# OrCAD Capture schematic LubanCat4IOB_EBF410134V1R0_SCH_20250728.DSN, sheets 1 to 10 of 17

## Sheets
1 17 TYPE C Socket: size A3; title: 野火_EBF RK3588S BTB底板; rev: V0R3; note: TYPE C Socket; note: https://yehuosm.tmall.com
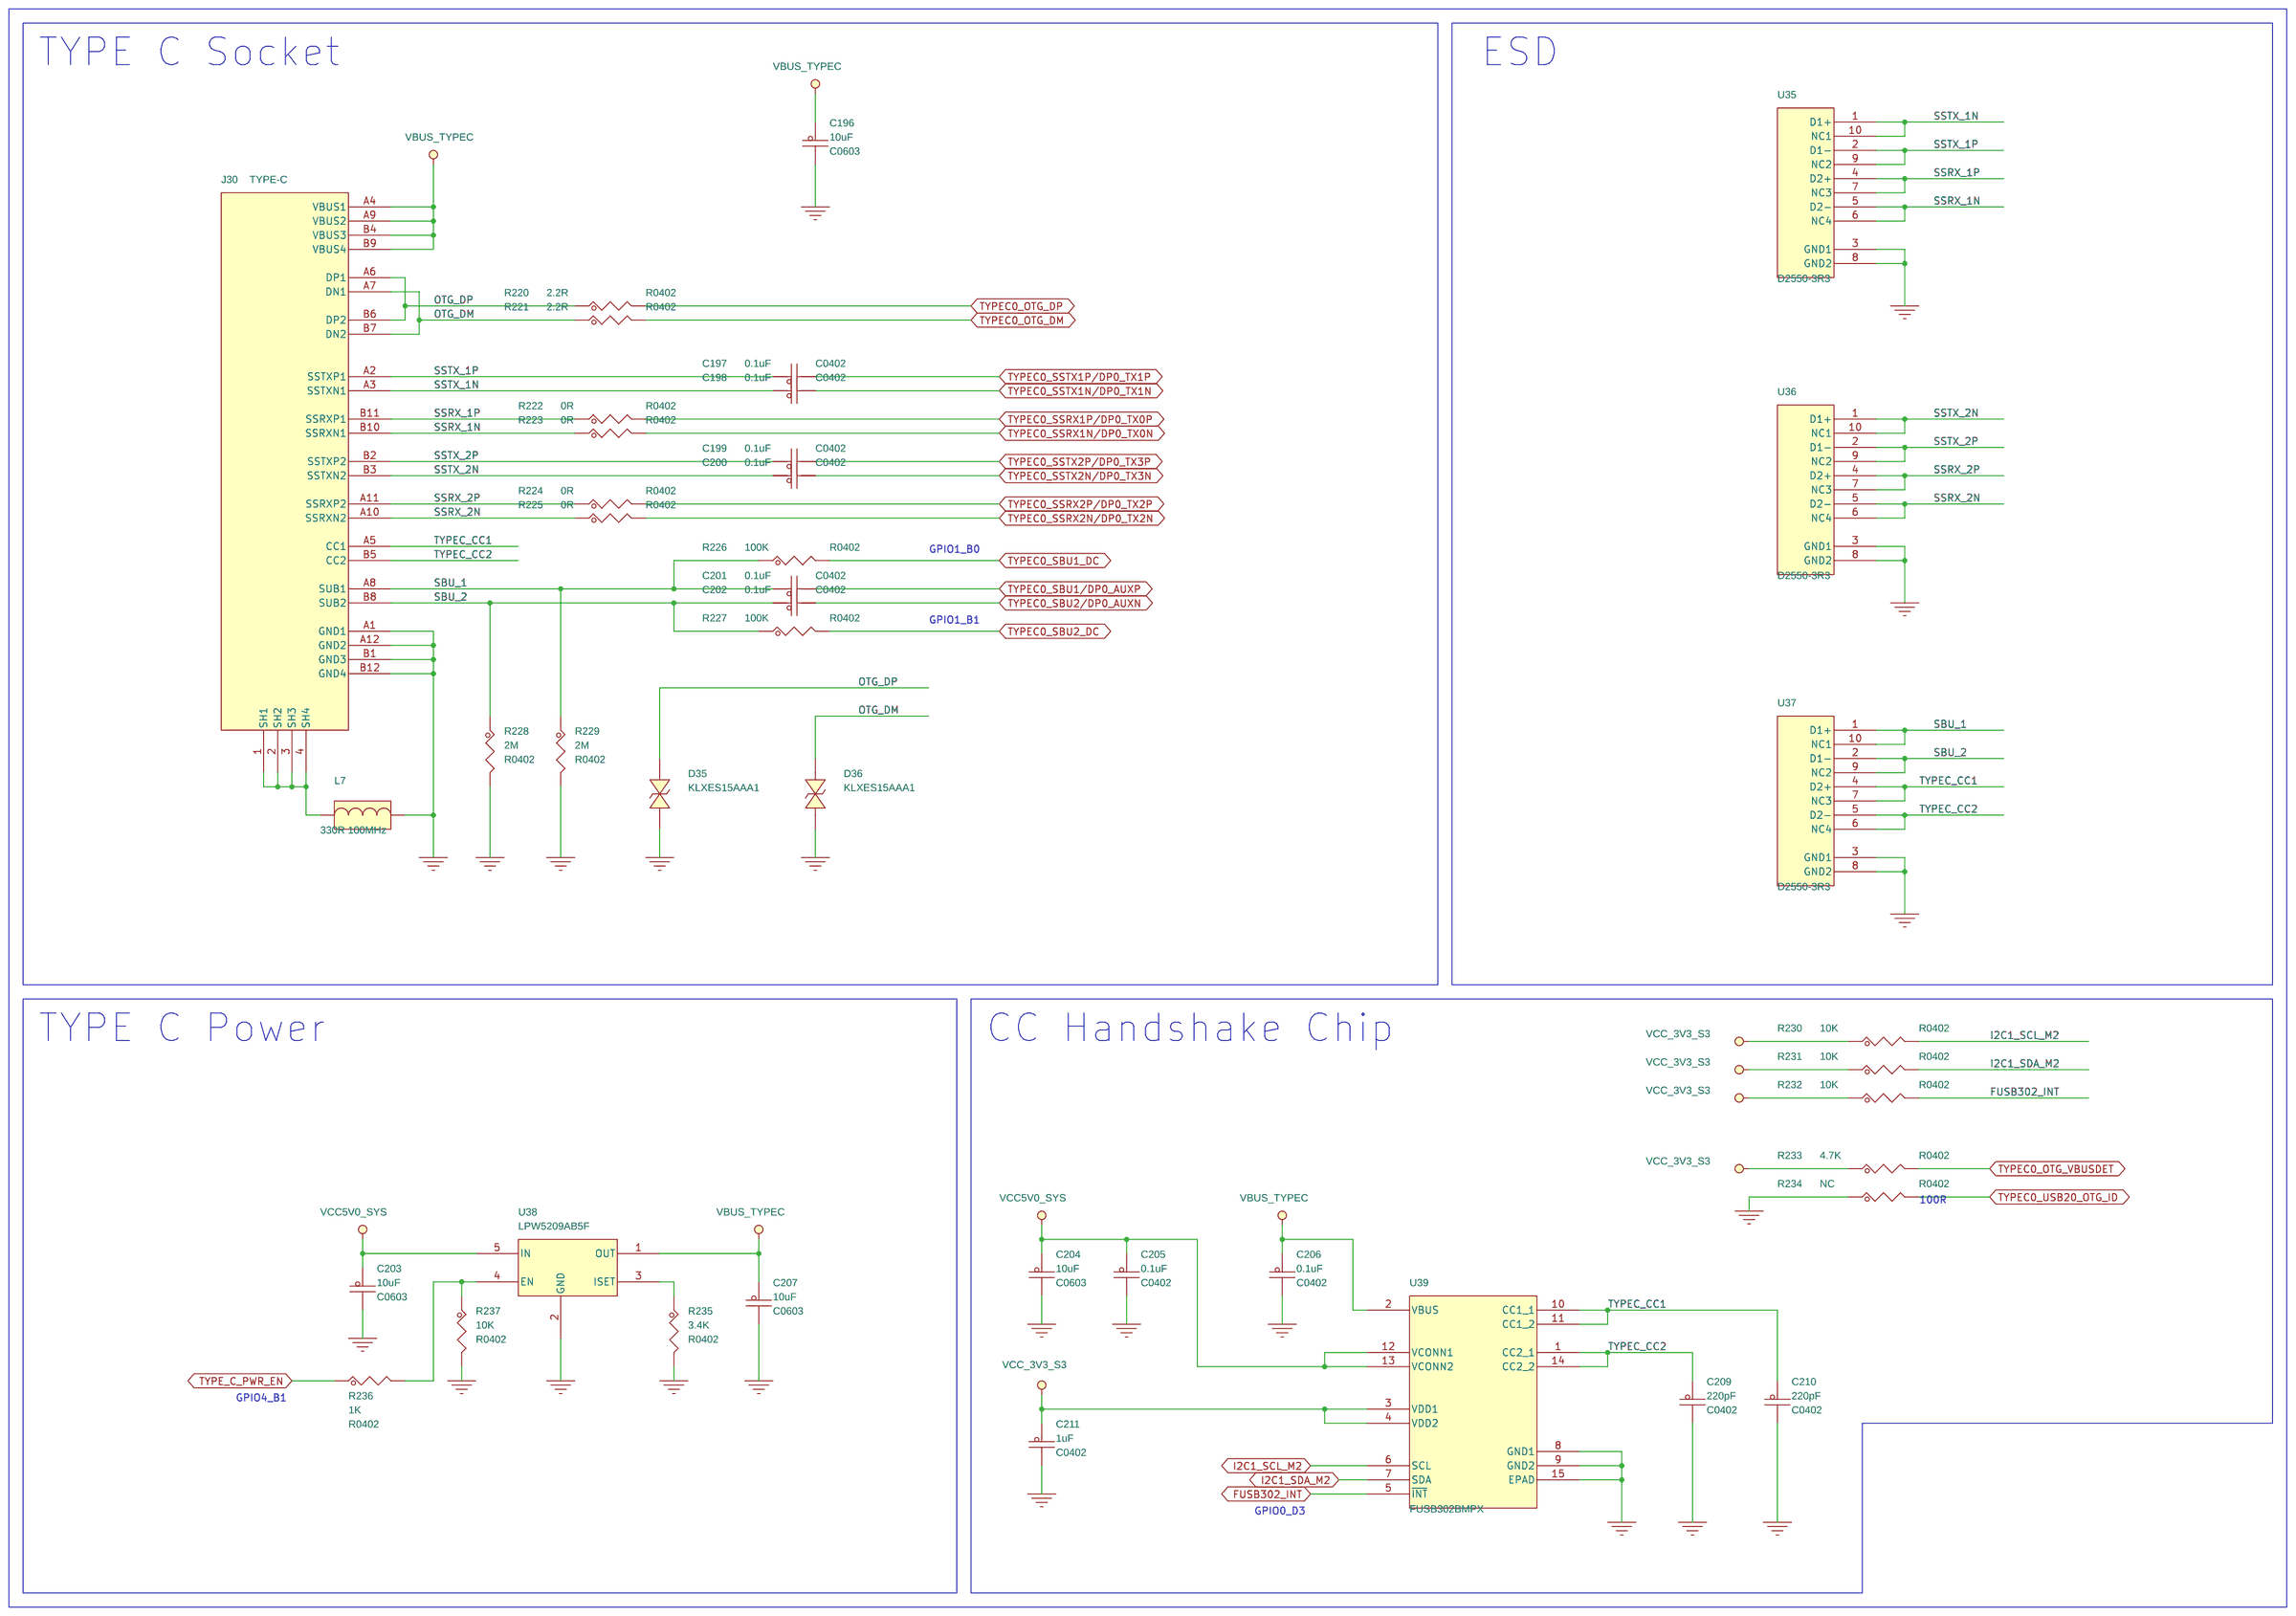
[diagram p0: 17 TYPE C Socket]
2 10 WLAN & BT: size A4; note: WLAN & BT
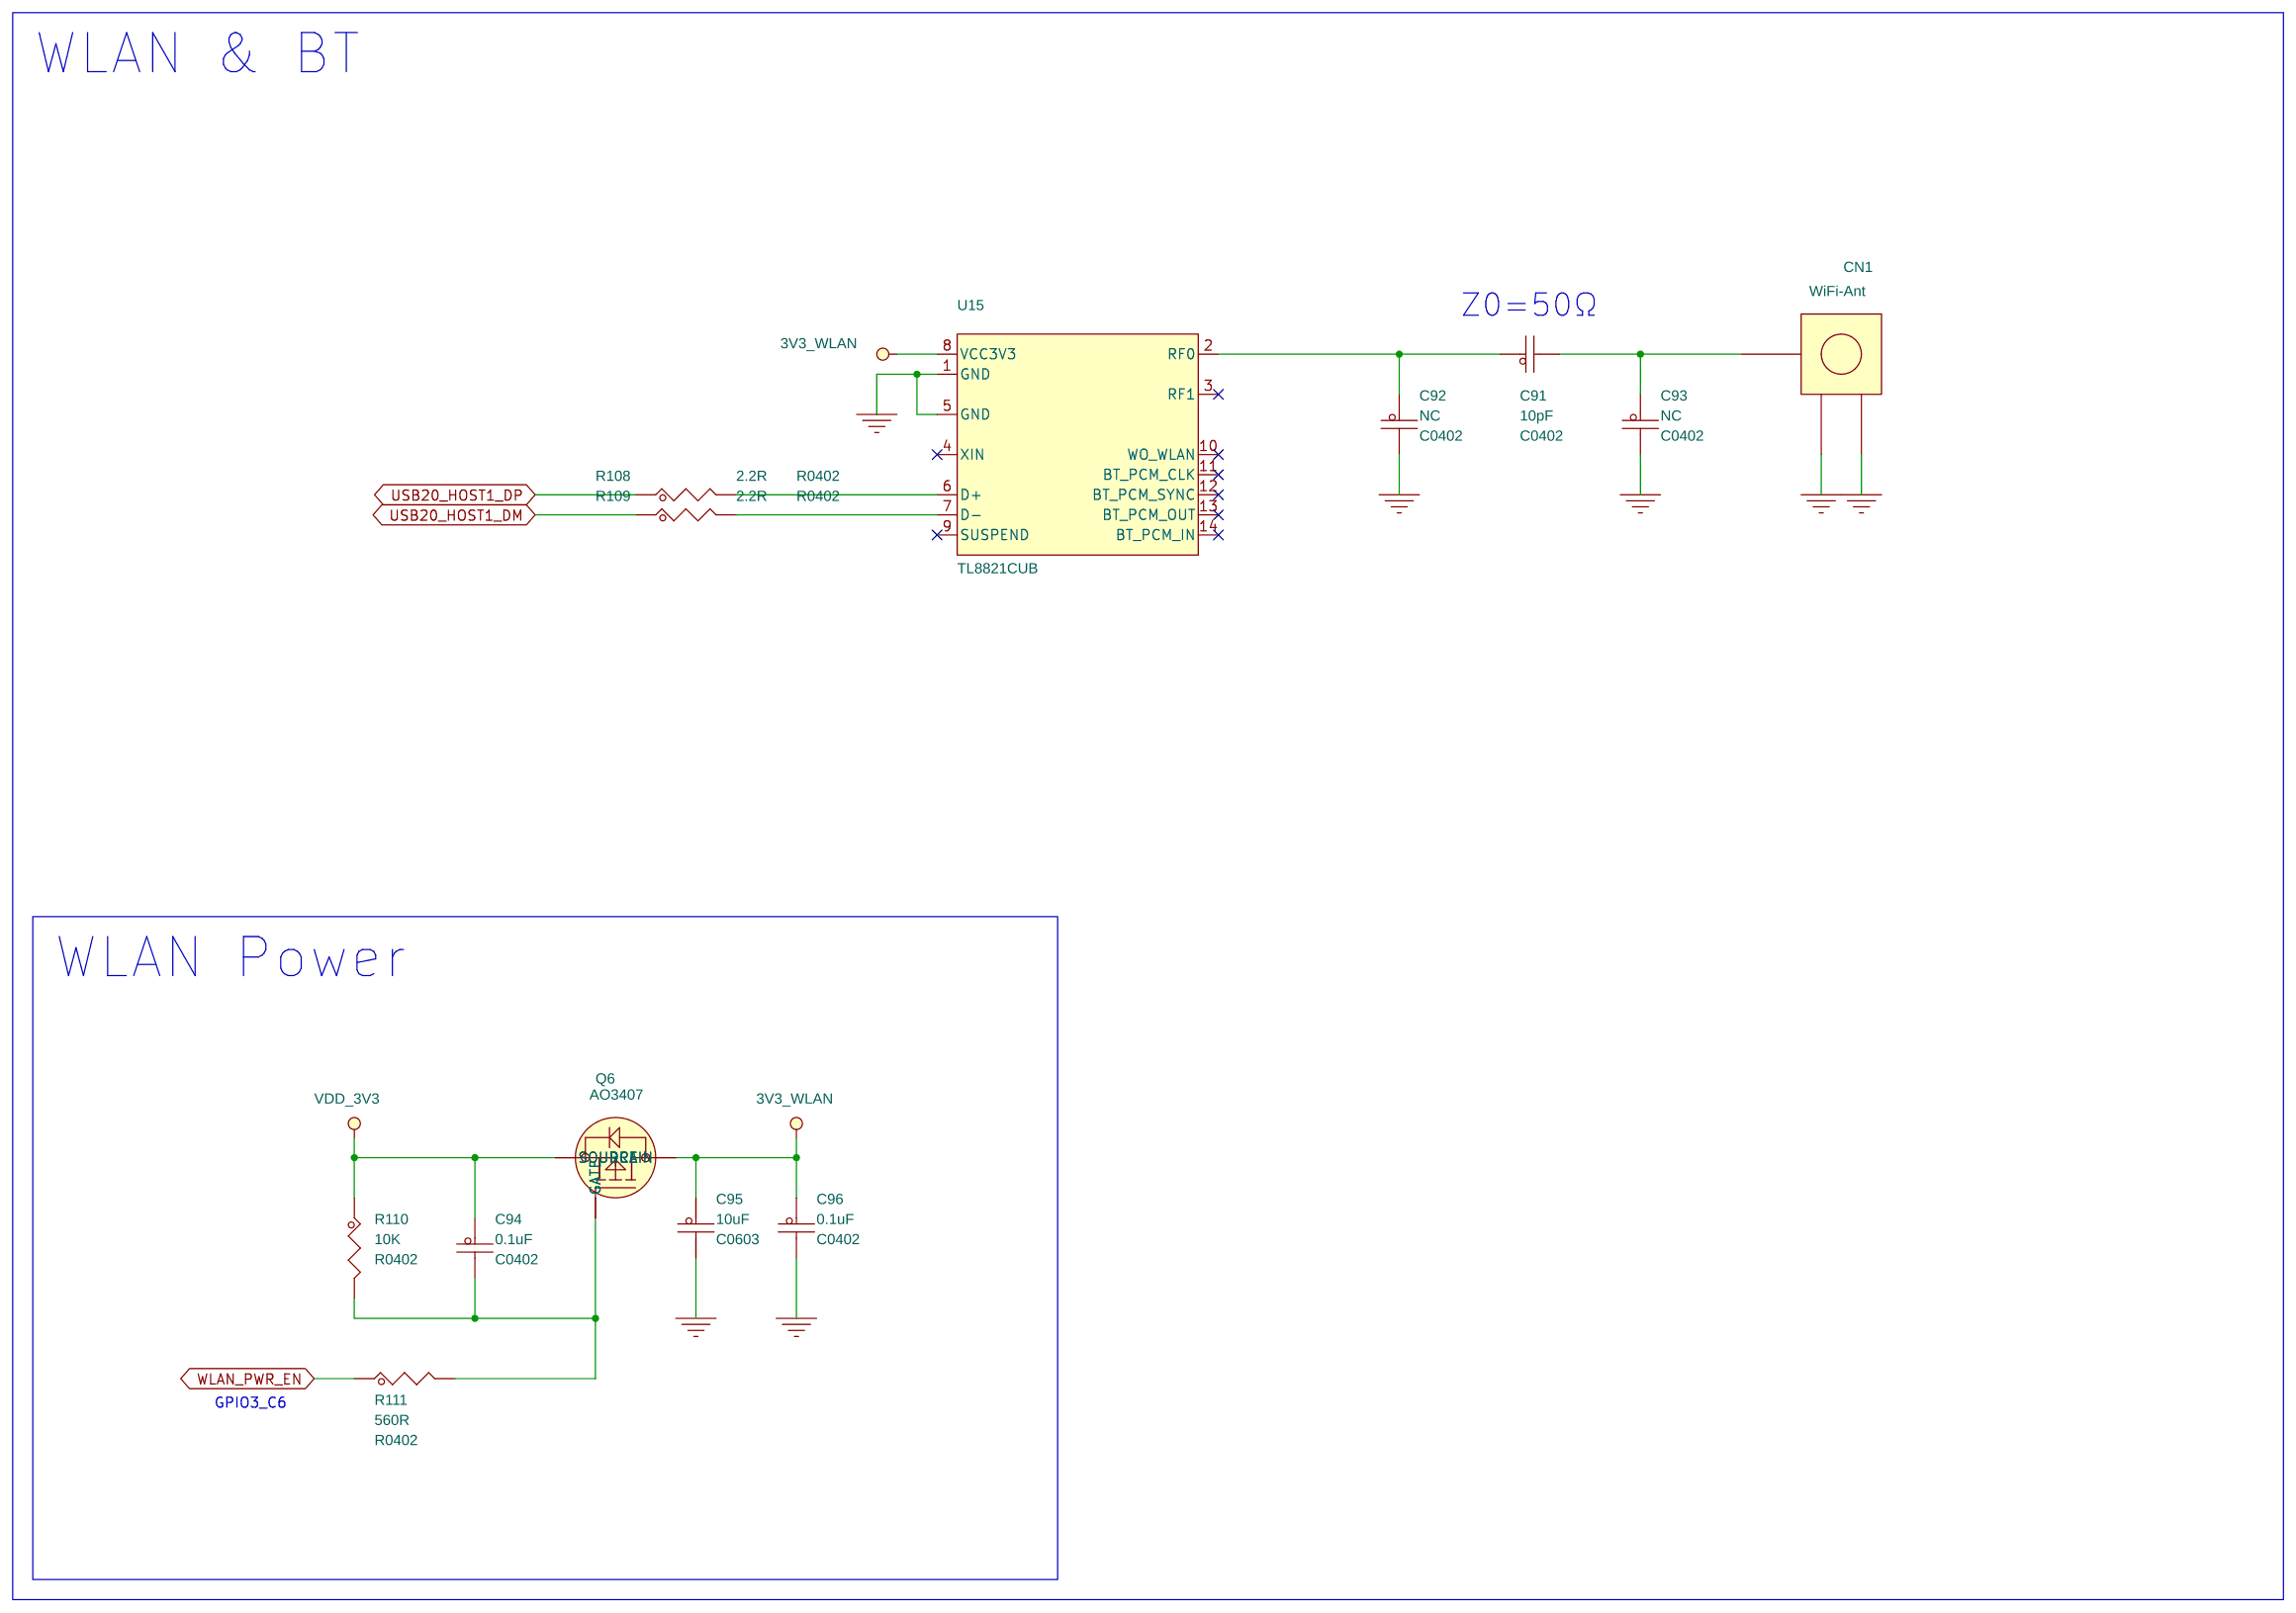
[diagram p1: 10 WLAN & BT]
3 01 Content: note: Content
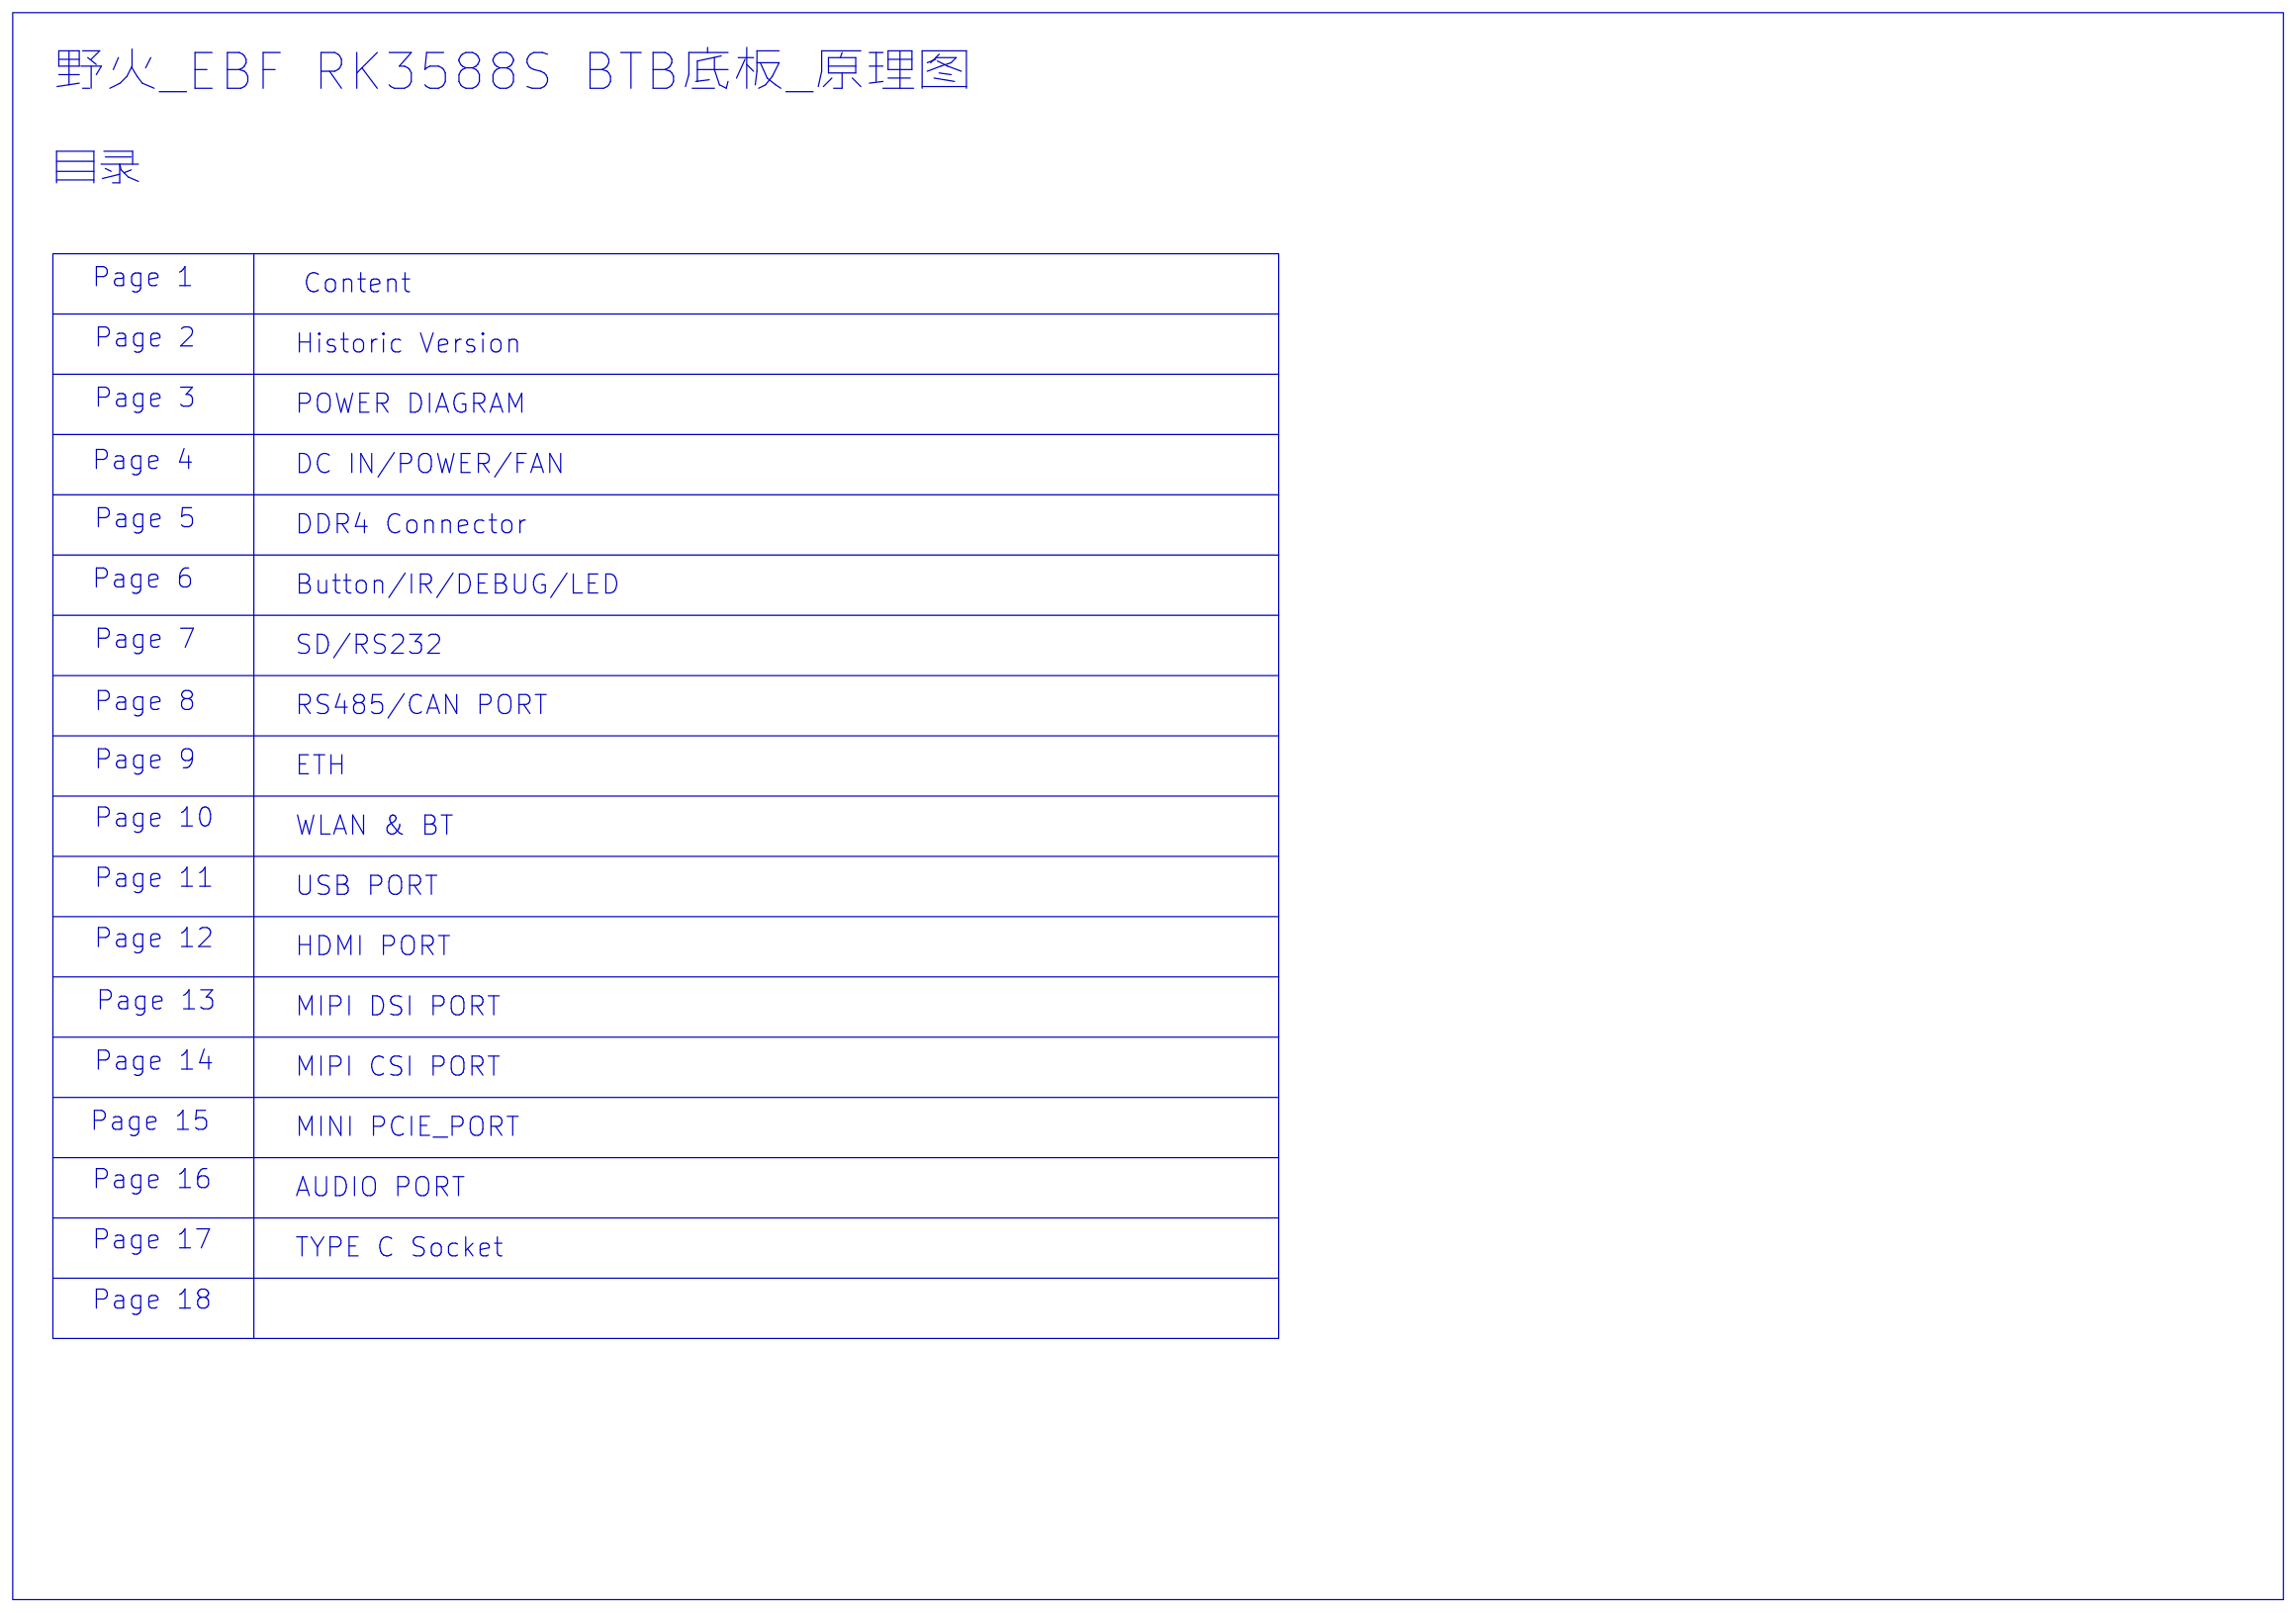
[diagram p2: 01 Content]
4 02 Historic Version: note: Historic Version
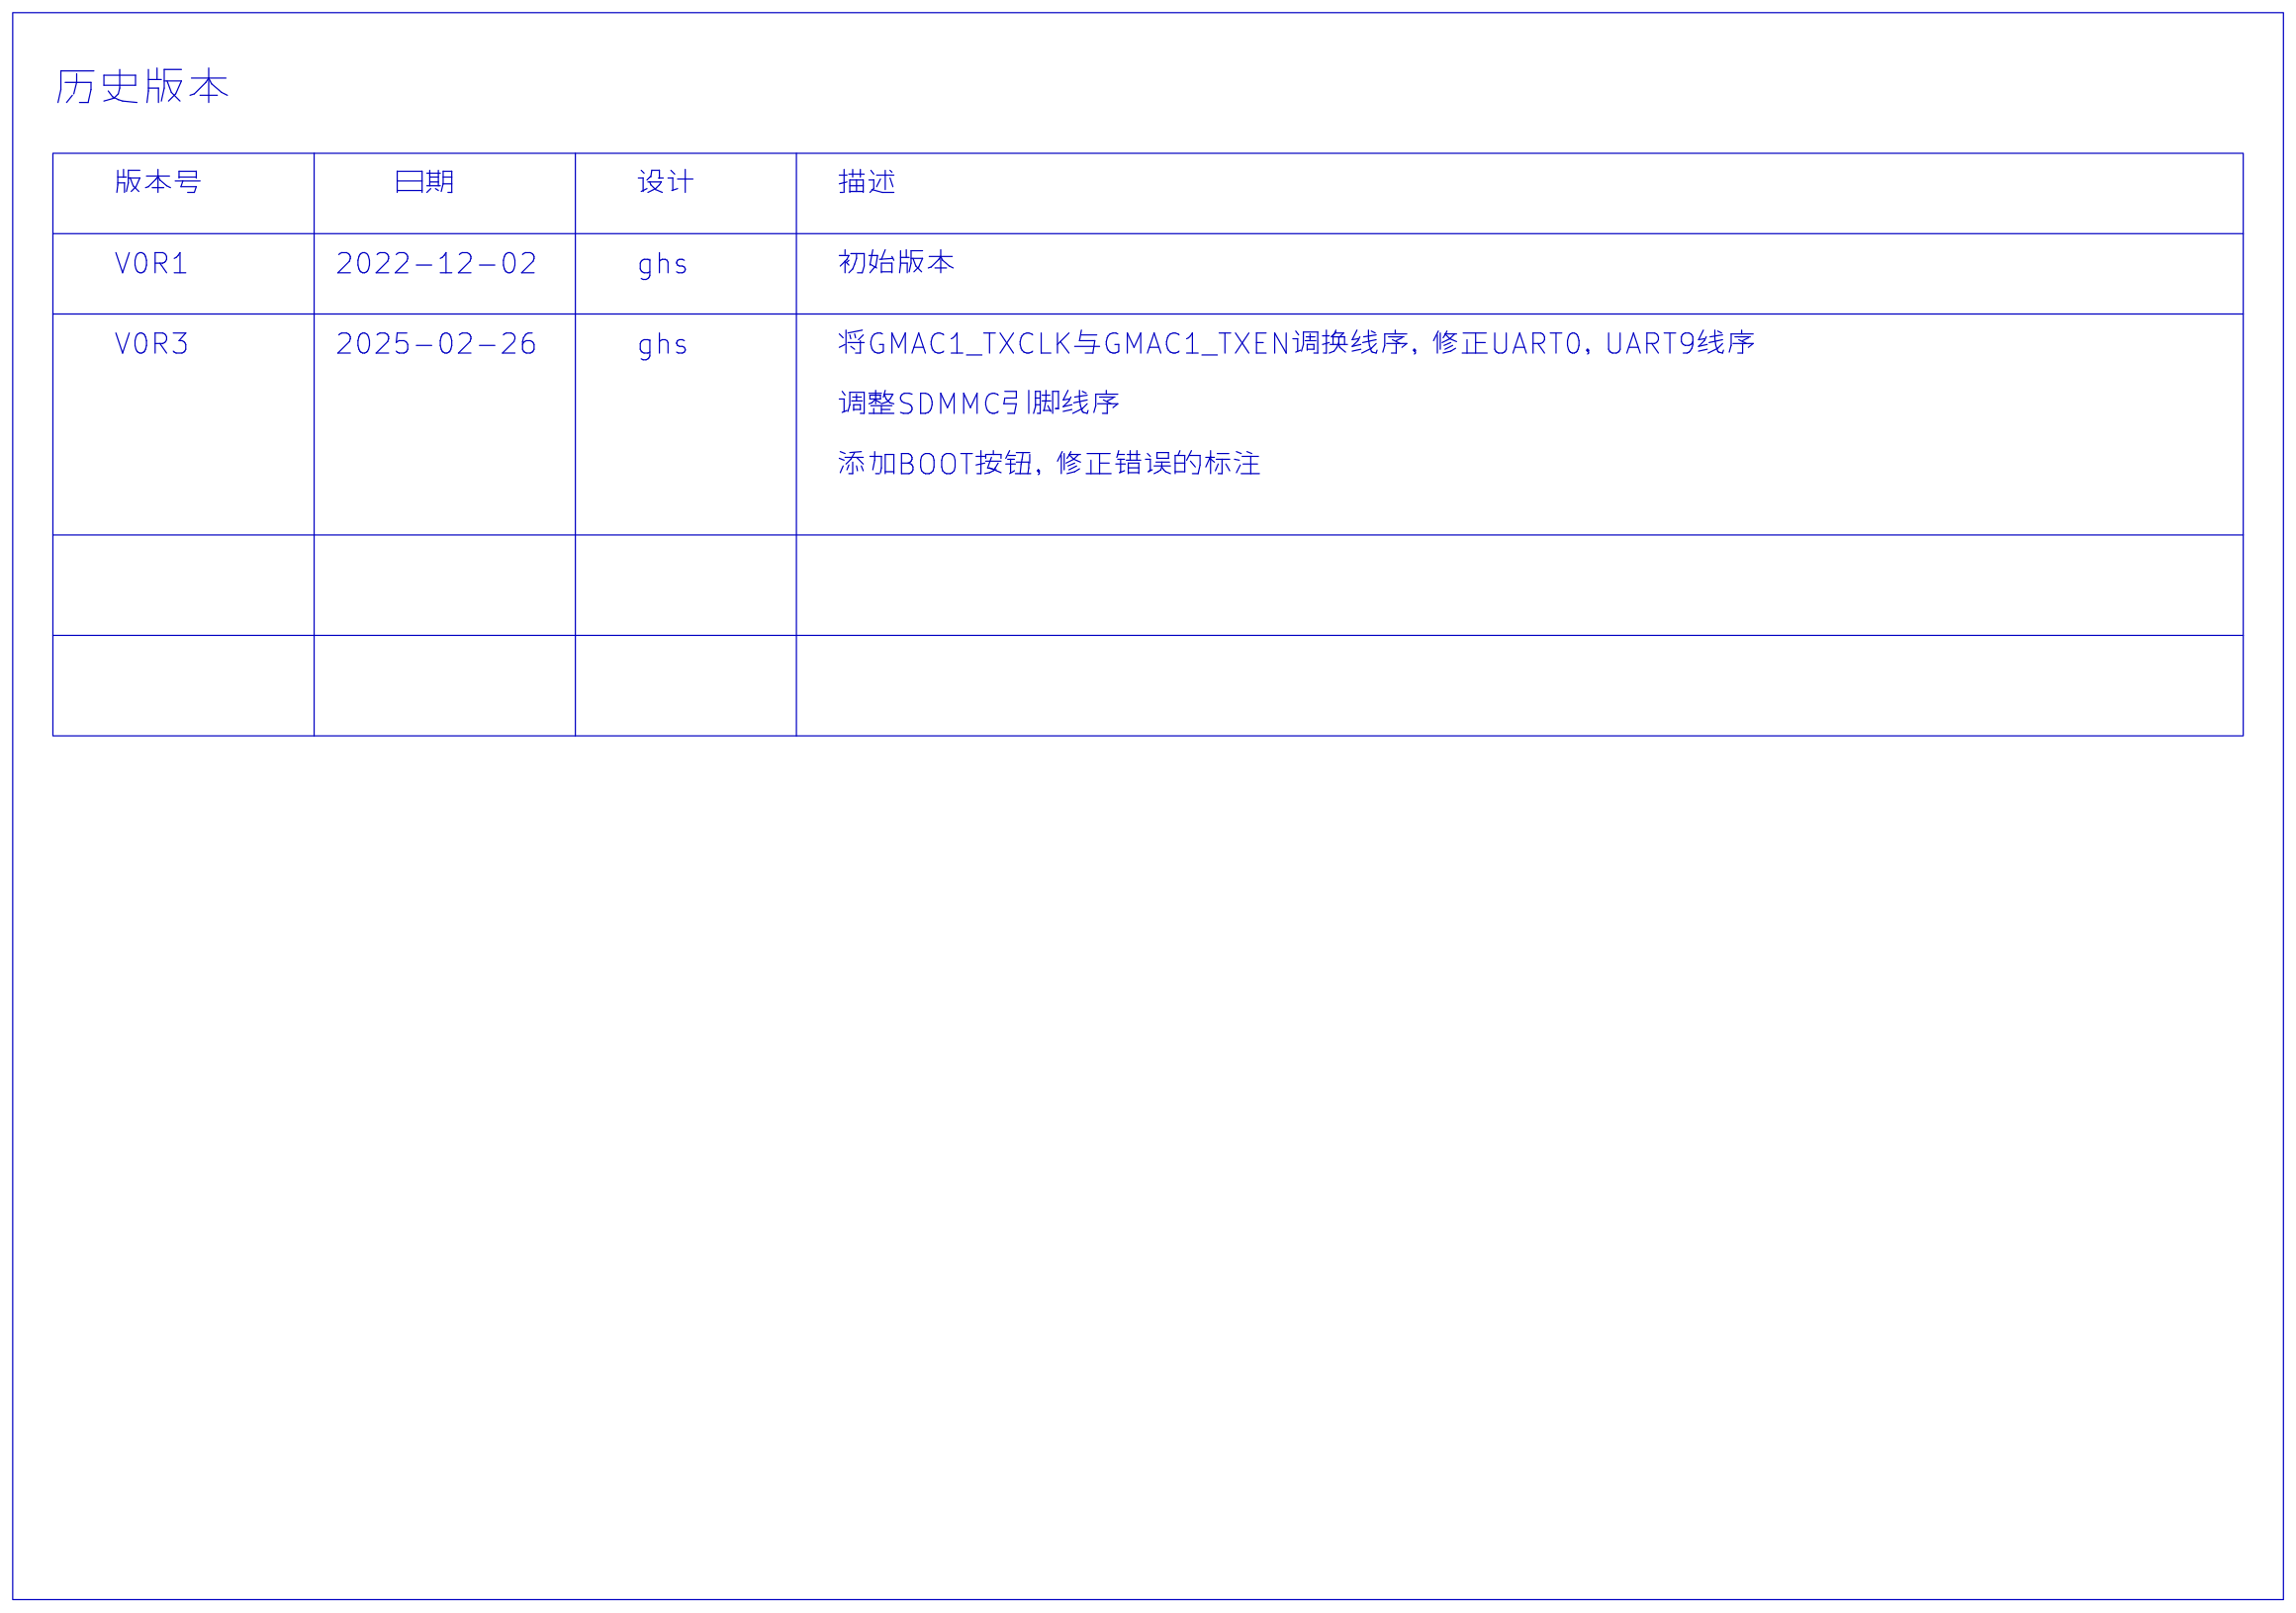
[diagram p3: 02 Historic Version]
5 03 POWER DIAGRAM: note: POWER DIAGRAM
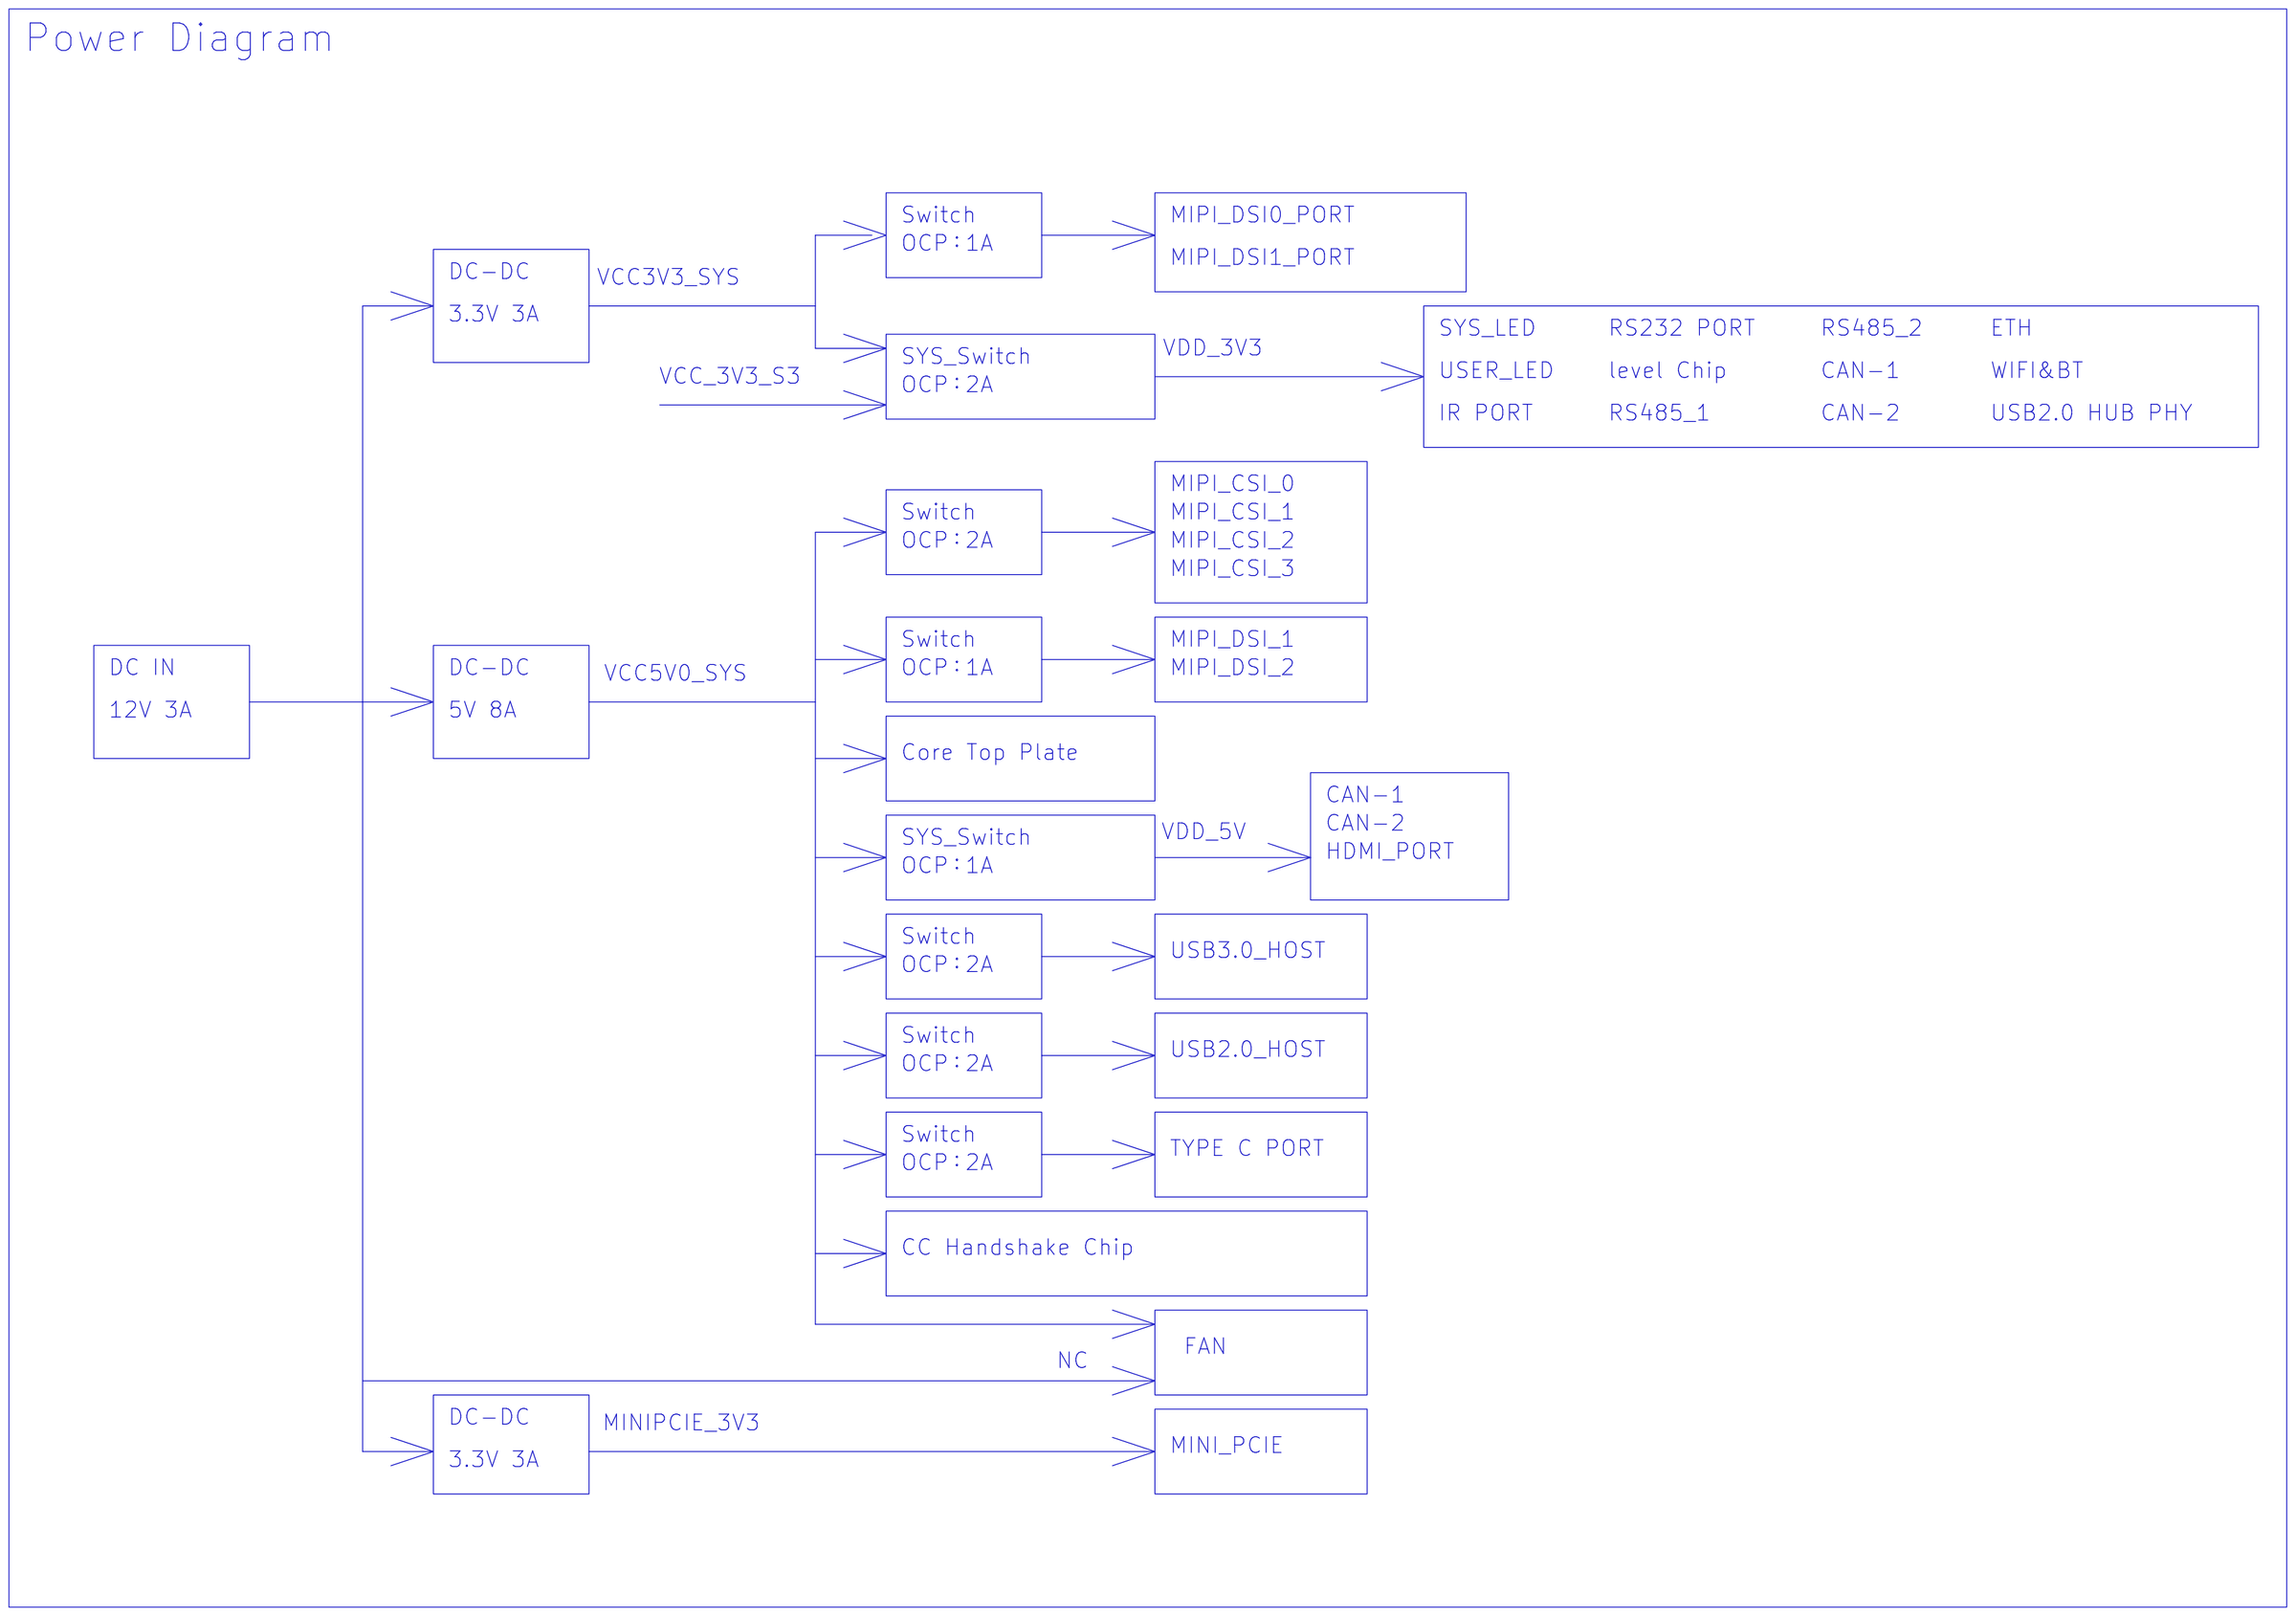
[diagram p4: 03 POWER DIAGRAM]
6 05 BTB Connector: size A2; note: BTB Connector
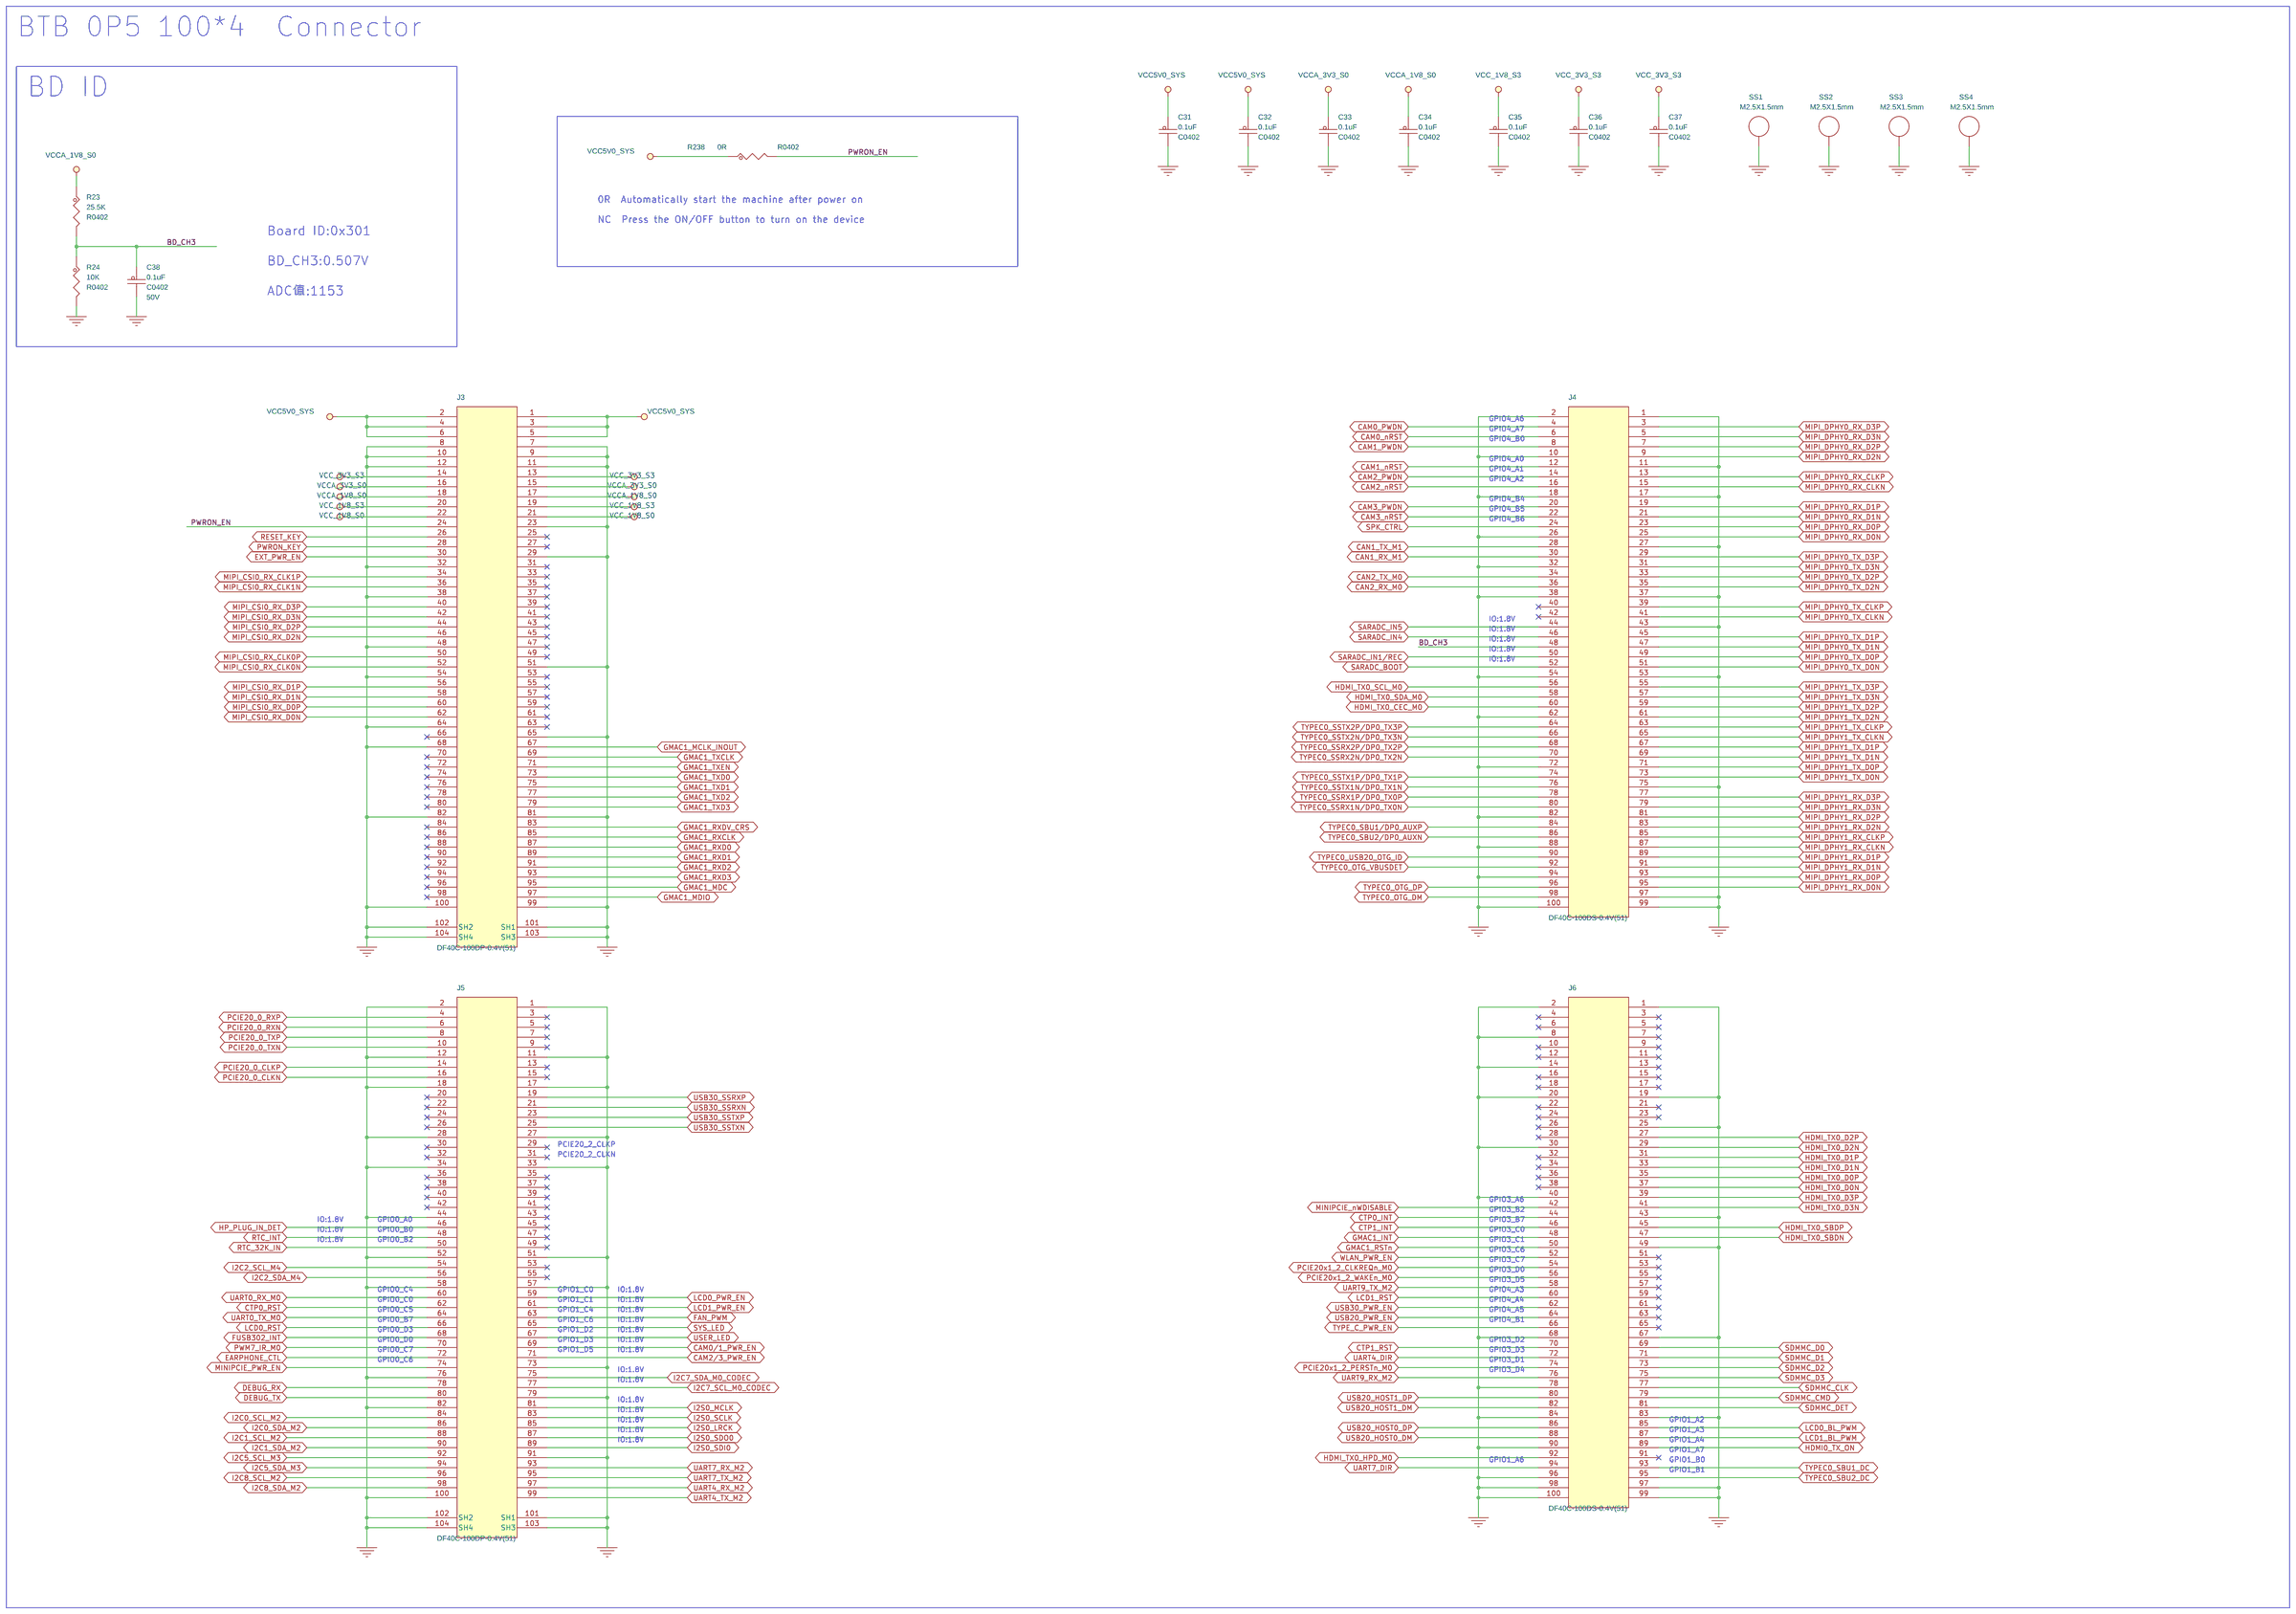
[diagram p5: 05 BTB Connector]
7 09 ETH: size A3; note: ETH
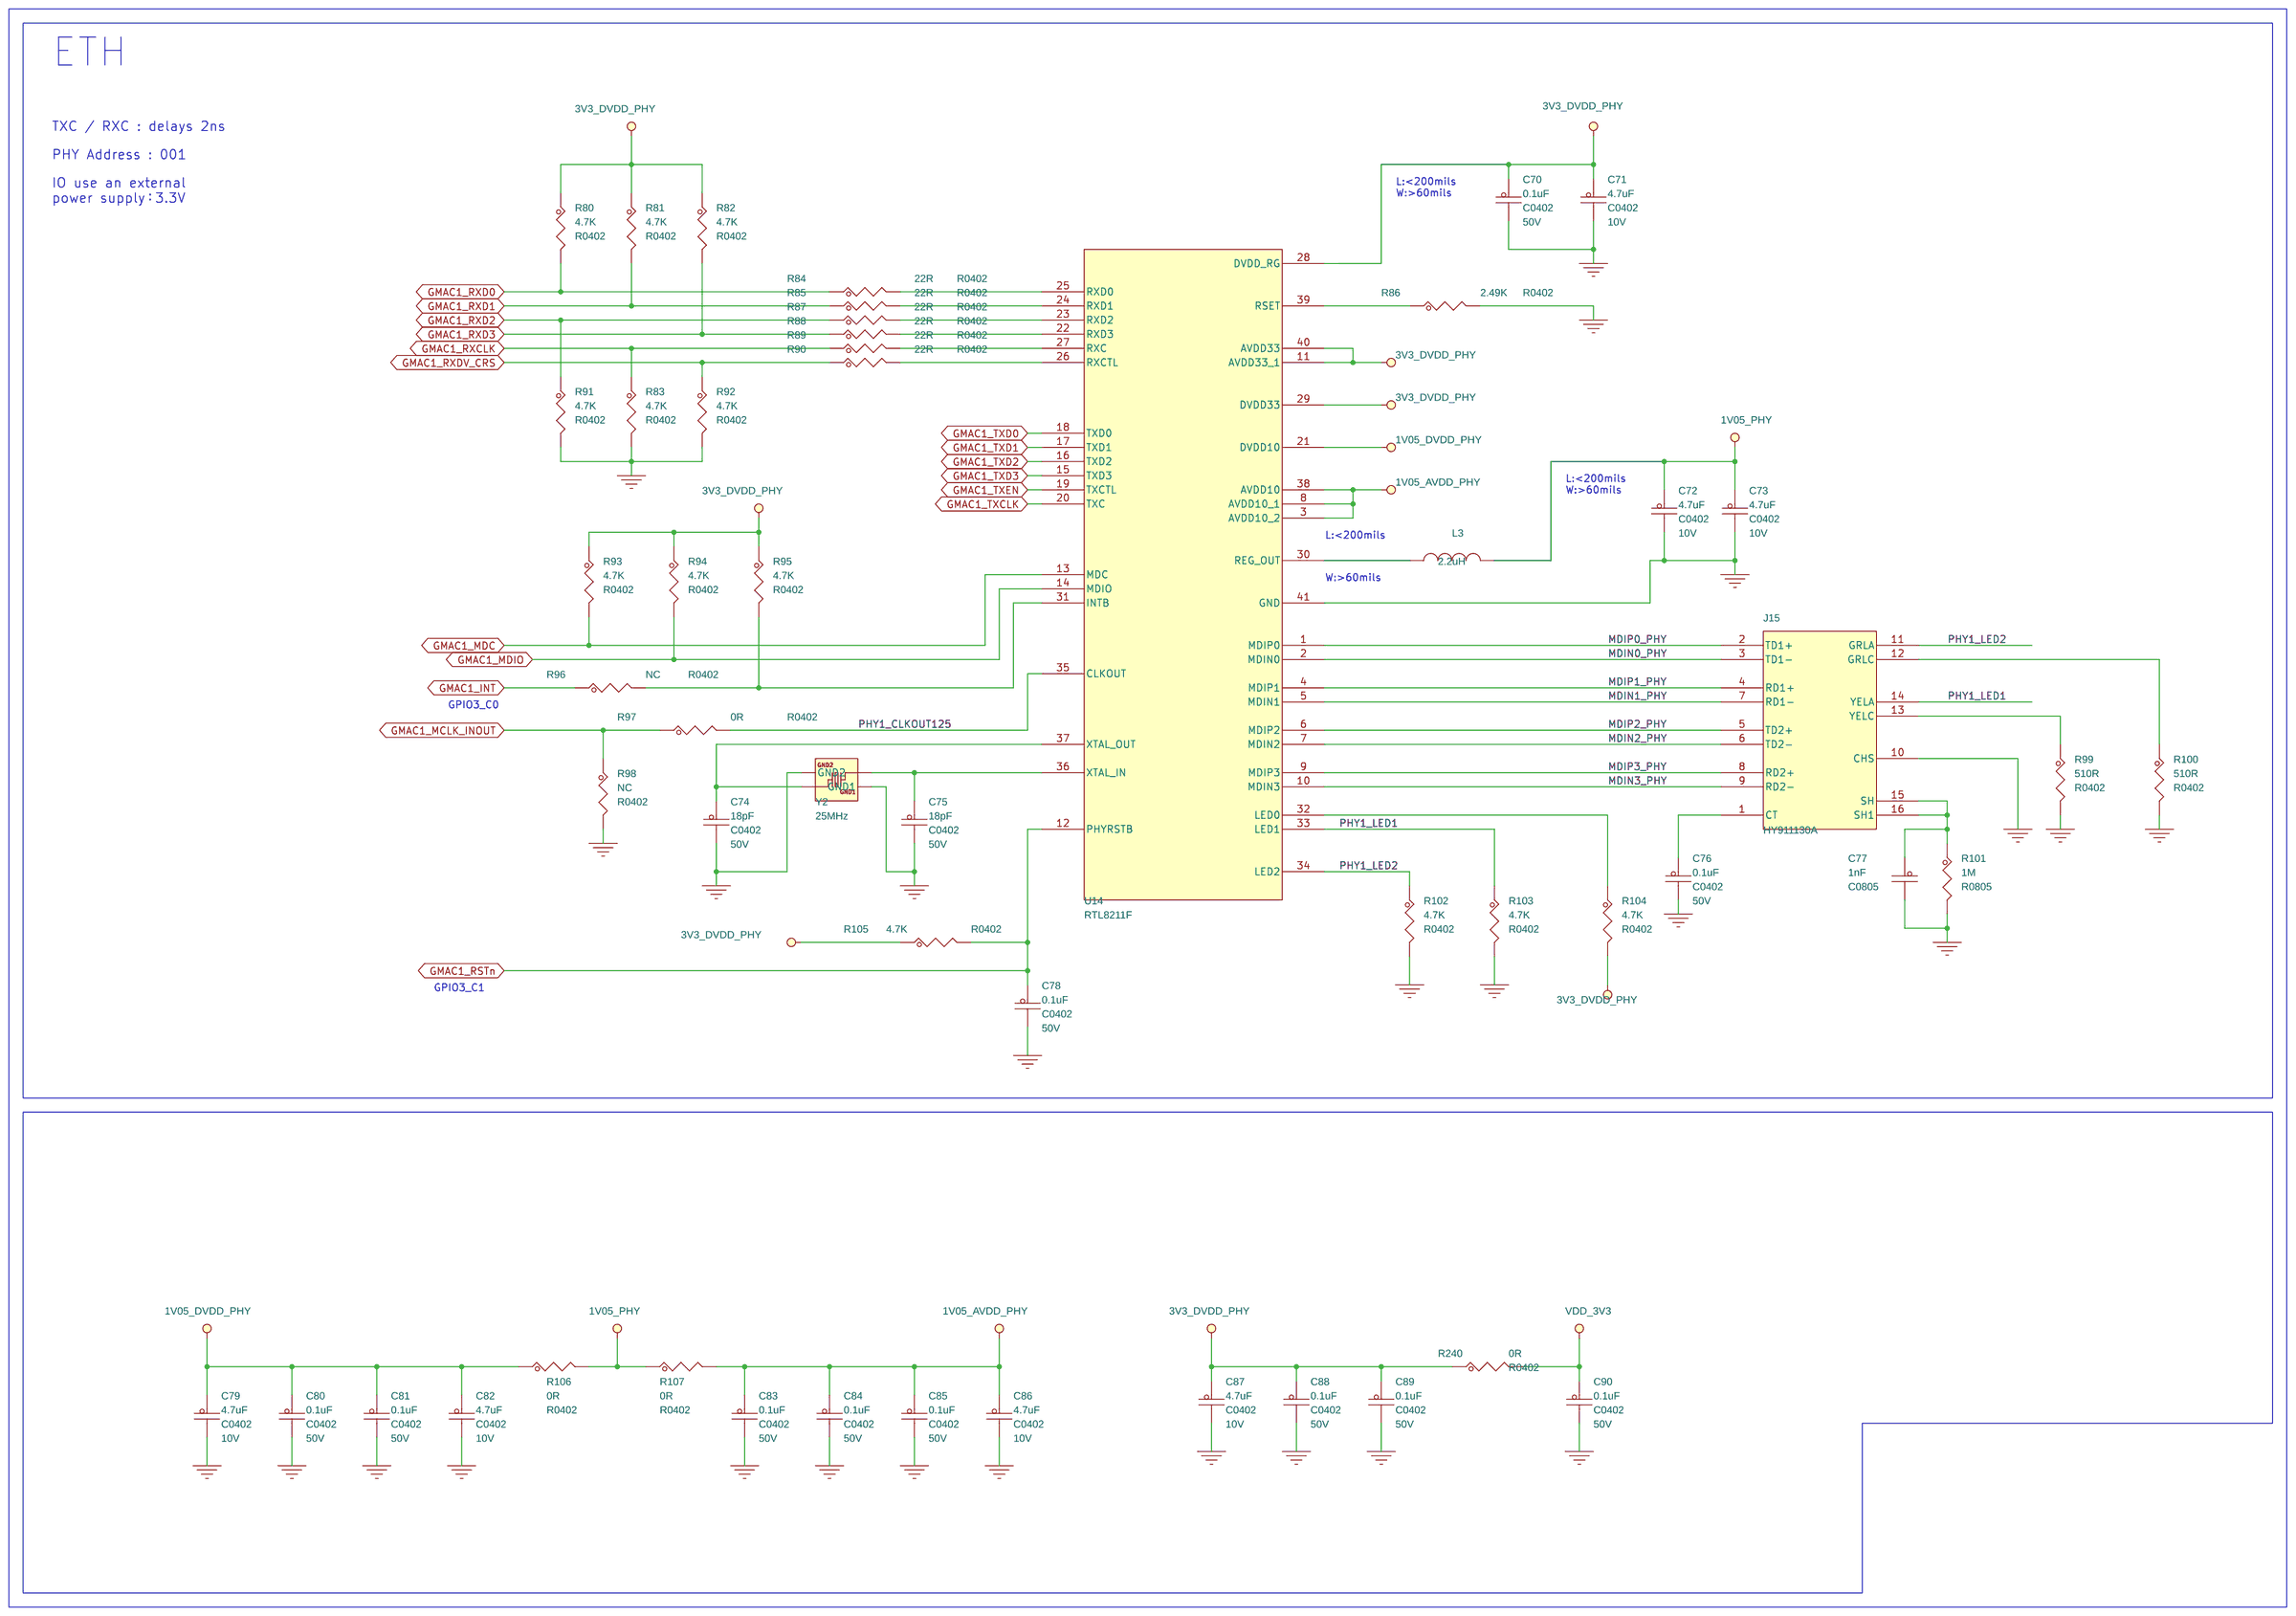
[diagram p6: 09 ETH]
8 11 USB PORT: size A3; note: USB PORT
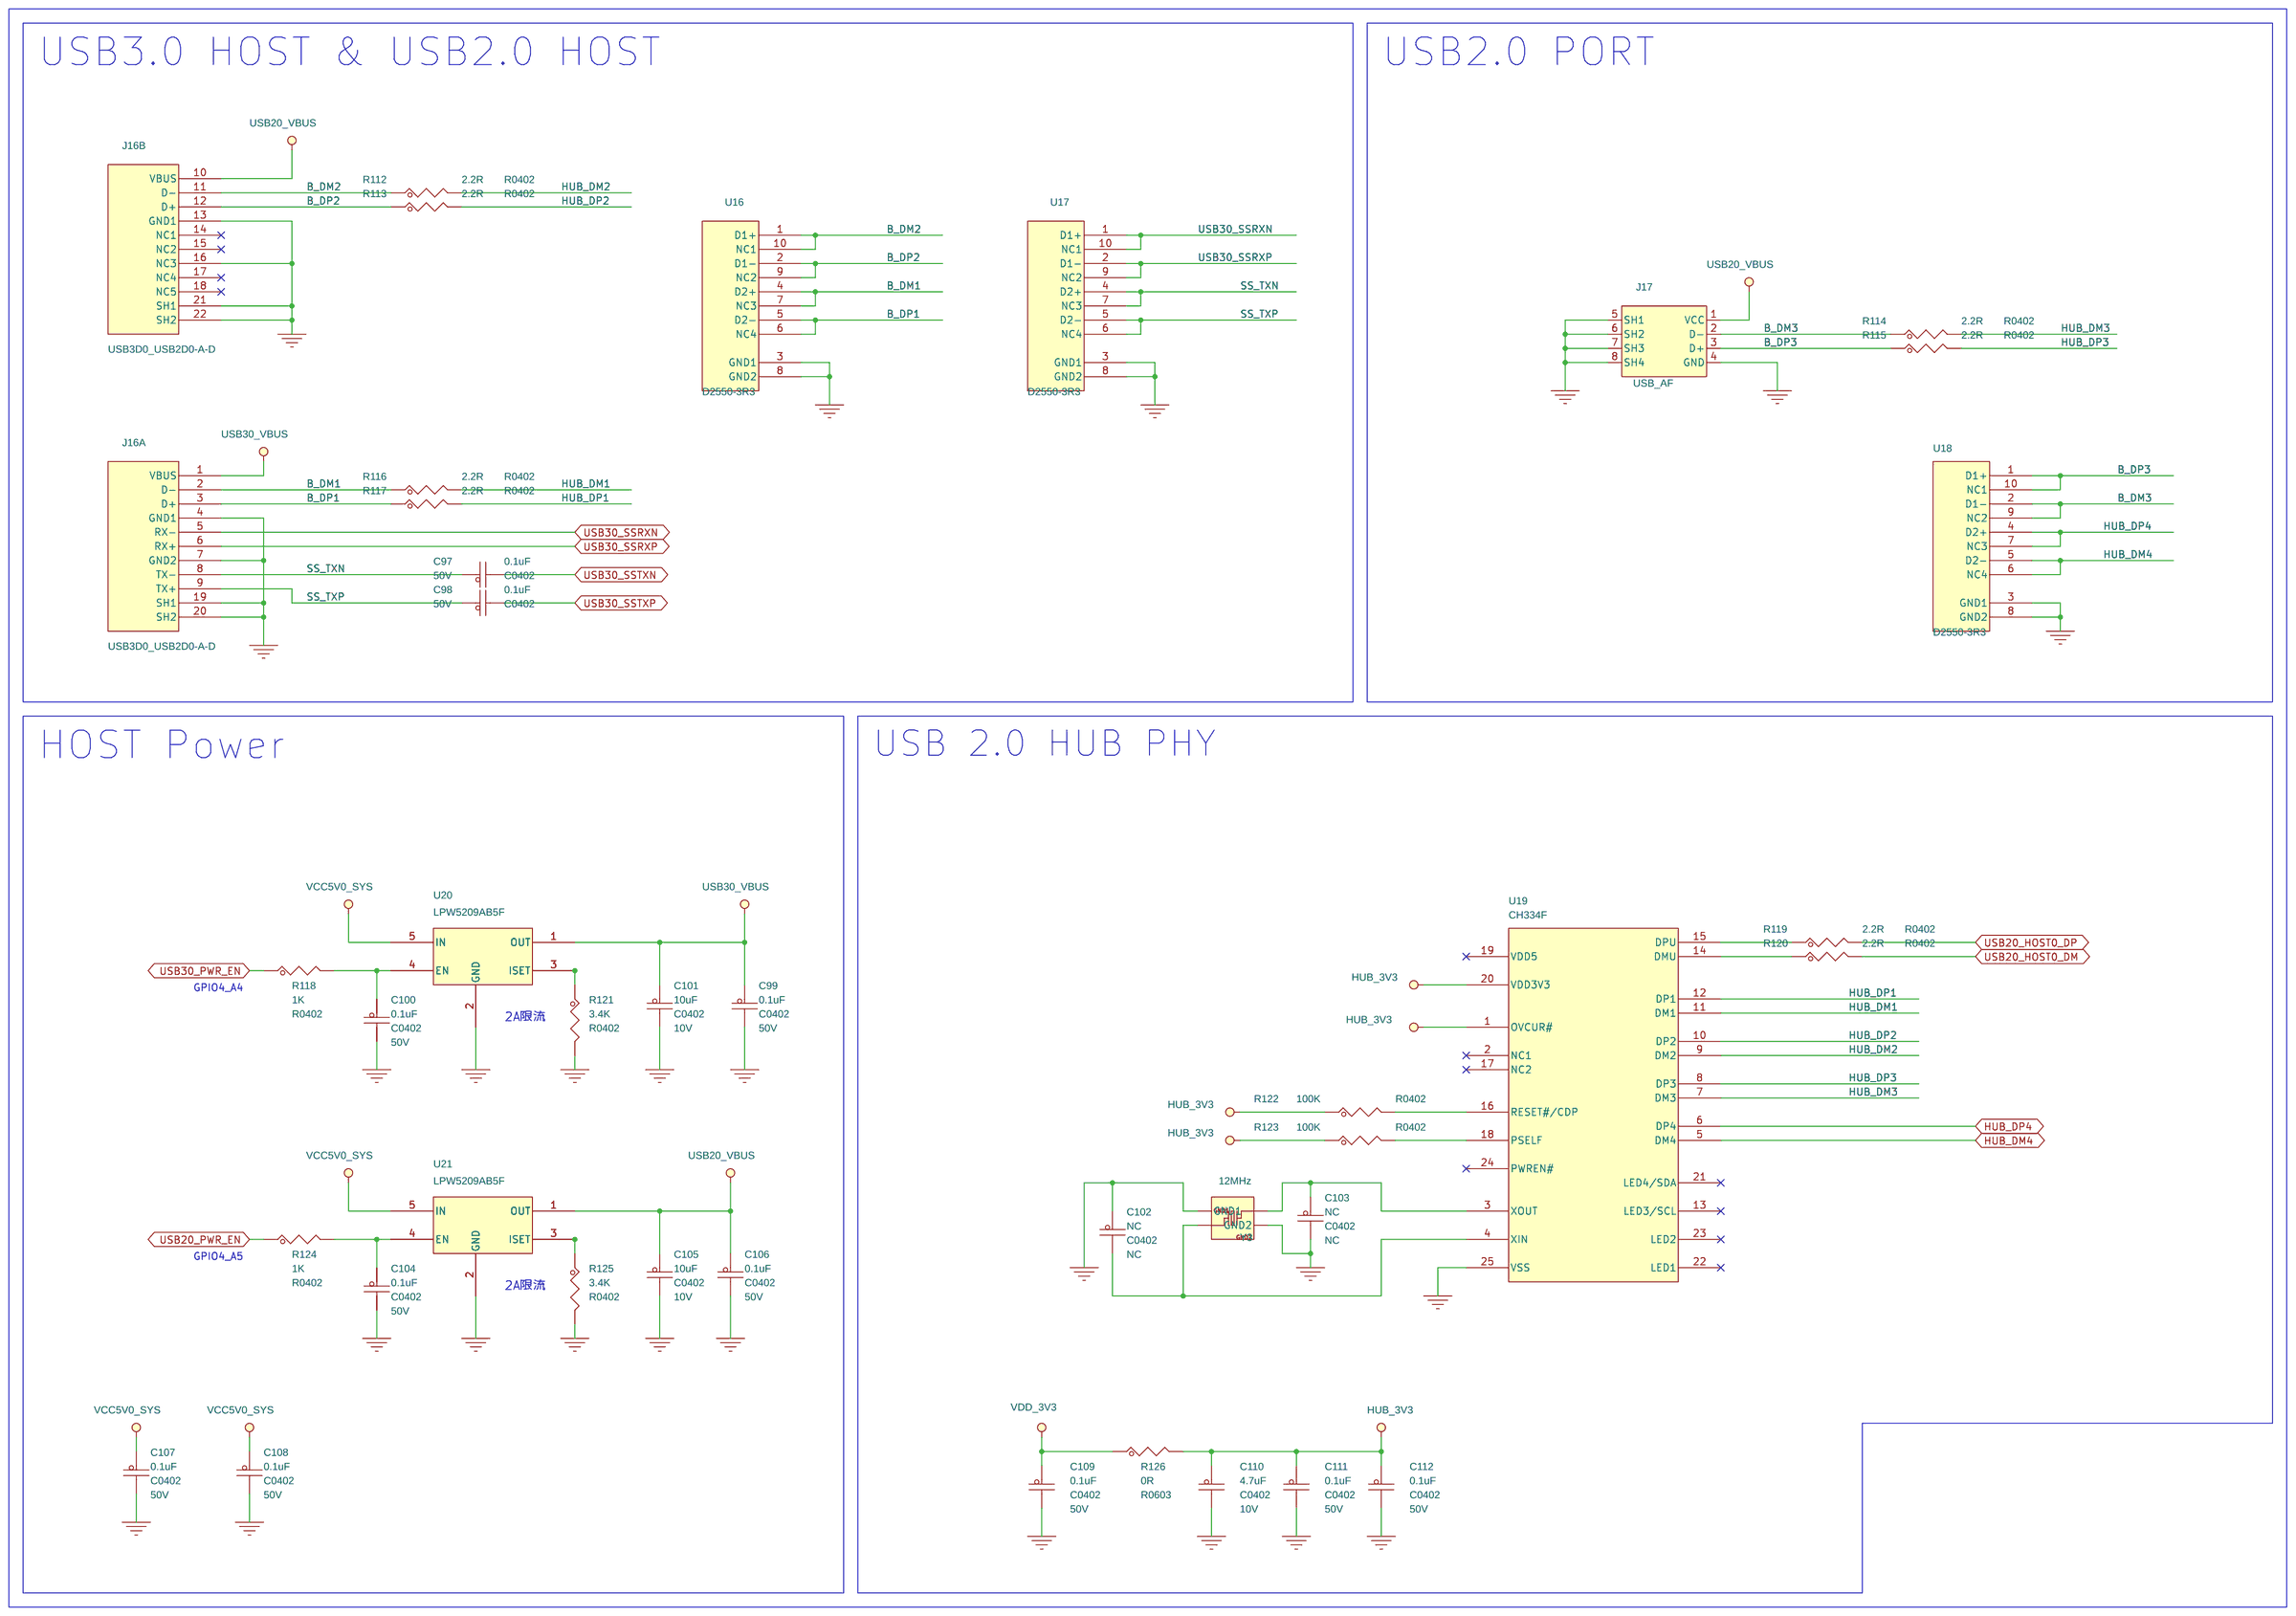
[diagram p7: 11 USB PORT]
9 12 HDMI PORT: size A3; note: HDMI PORT
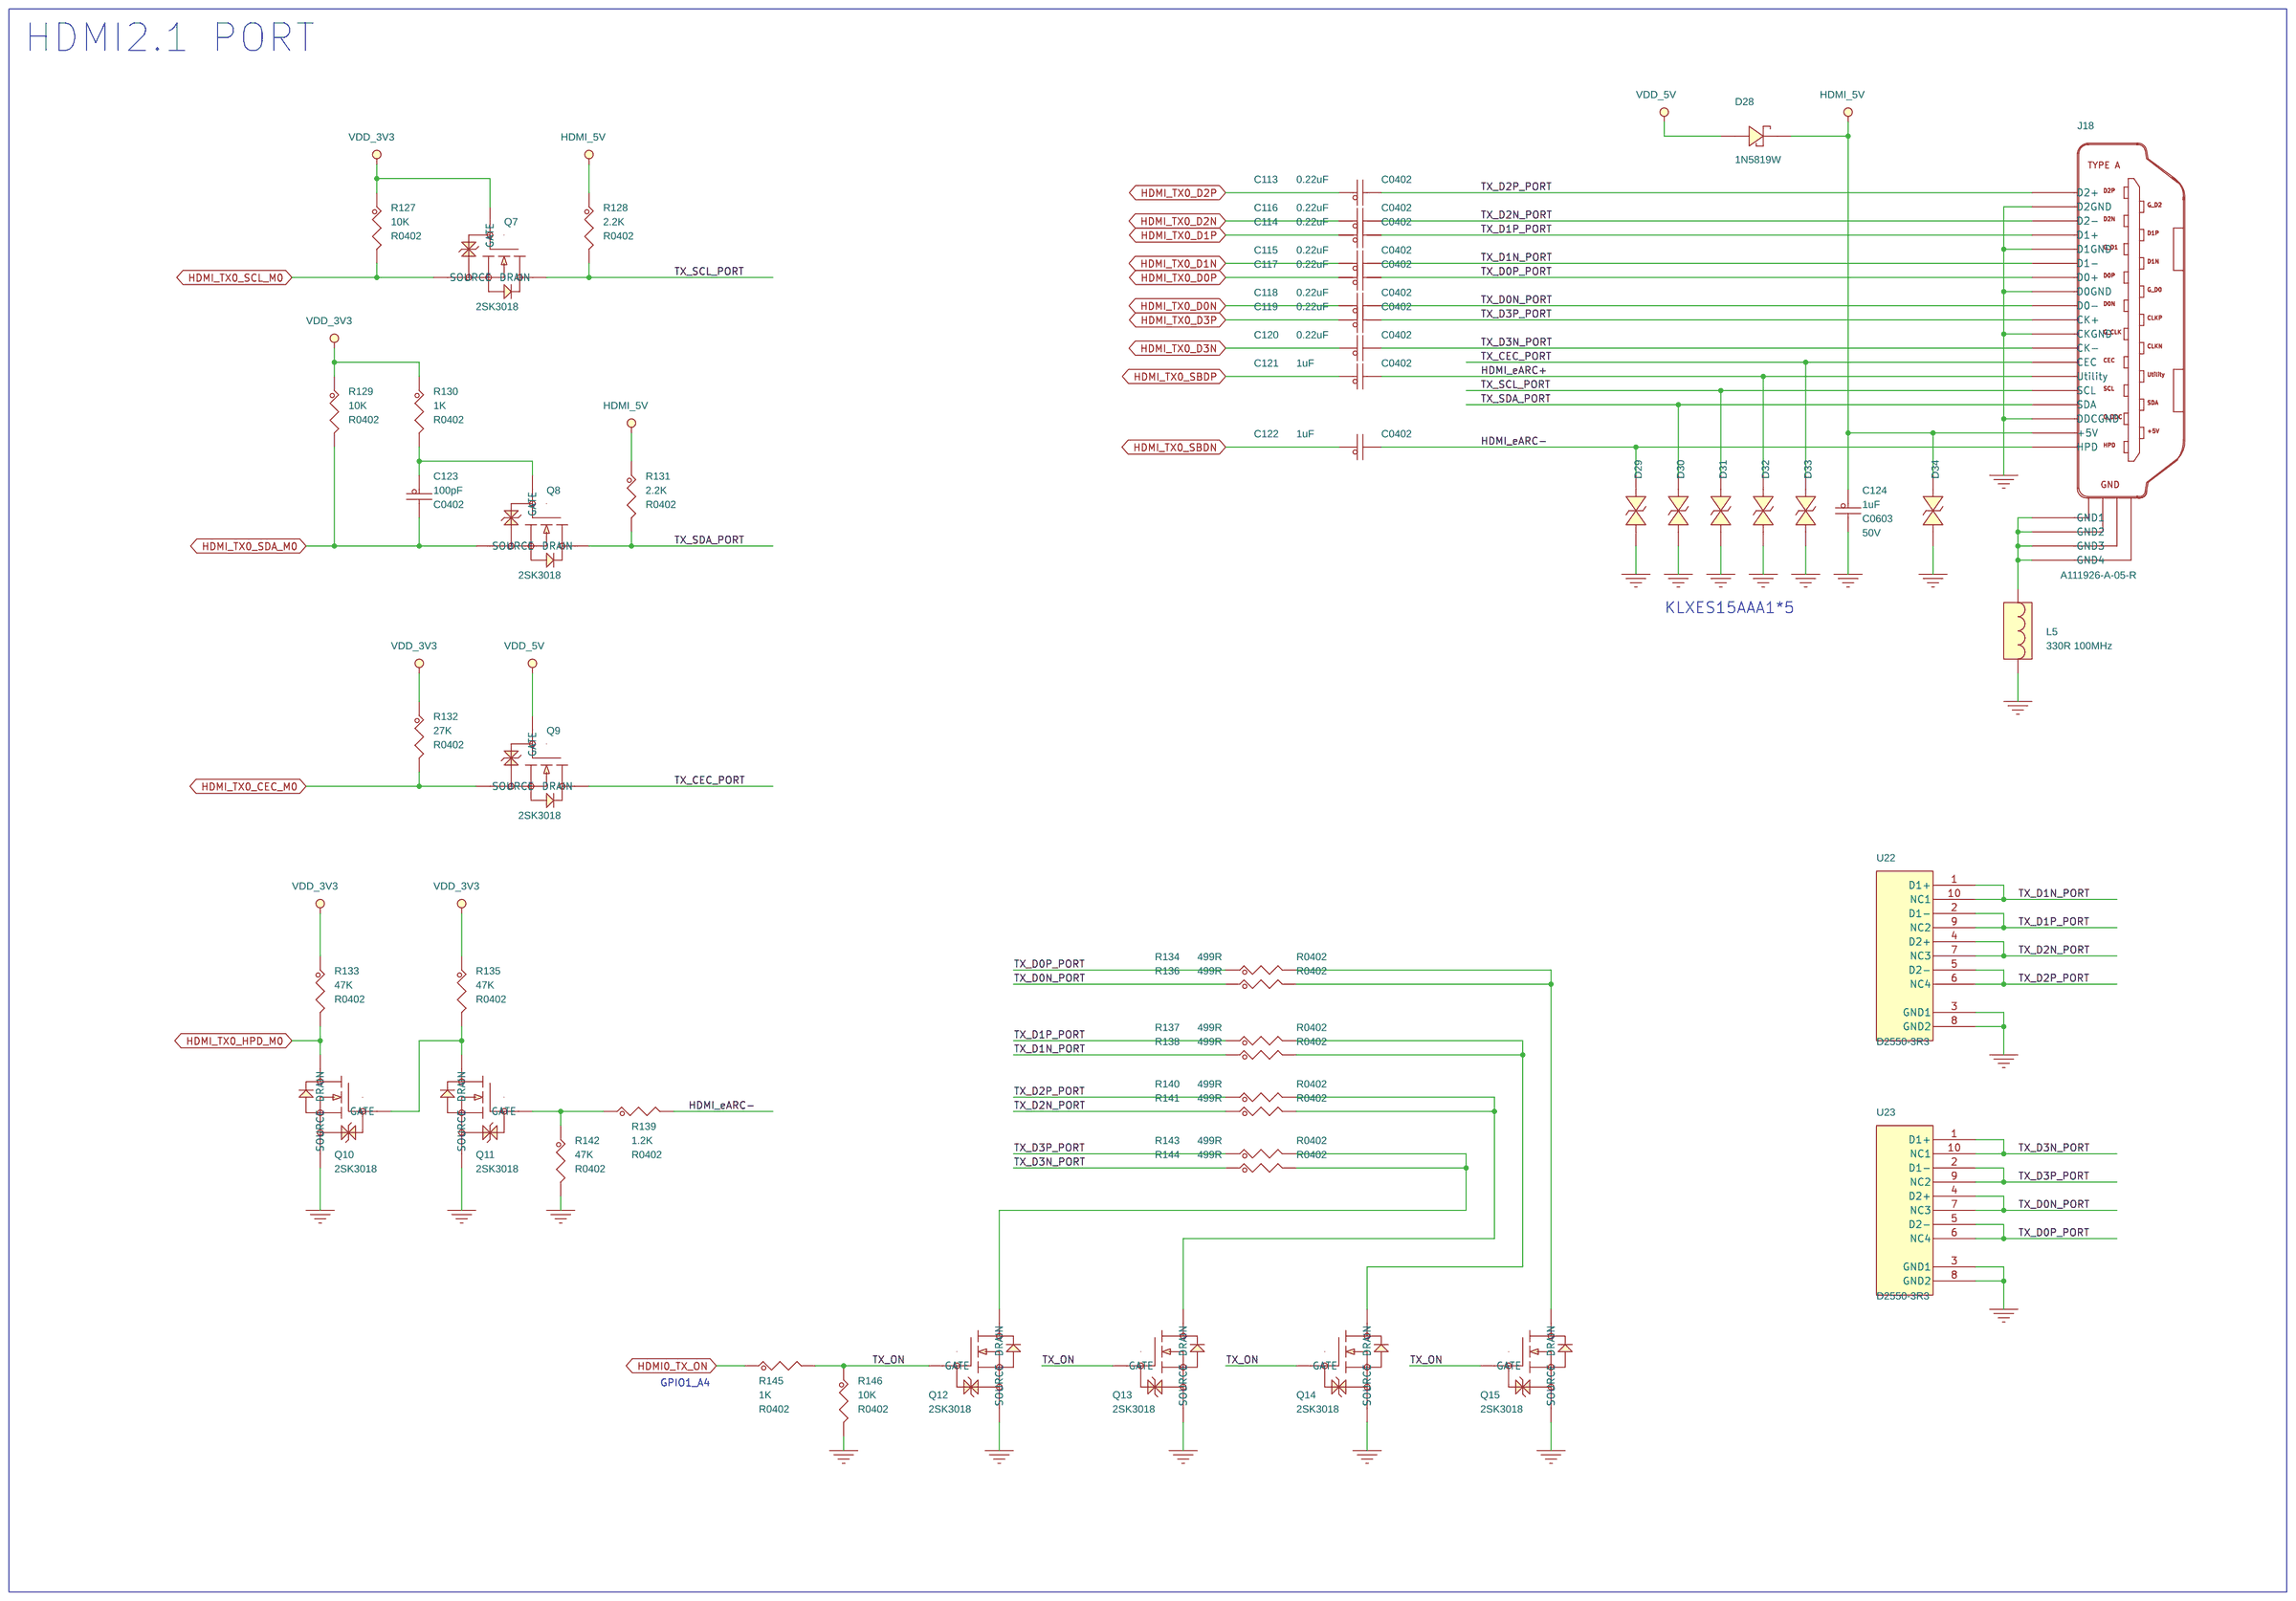
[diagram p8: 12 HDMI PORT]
10 13 MIPI DSI PORT: size A3; note: MIPI DSI PORT
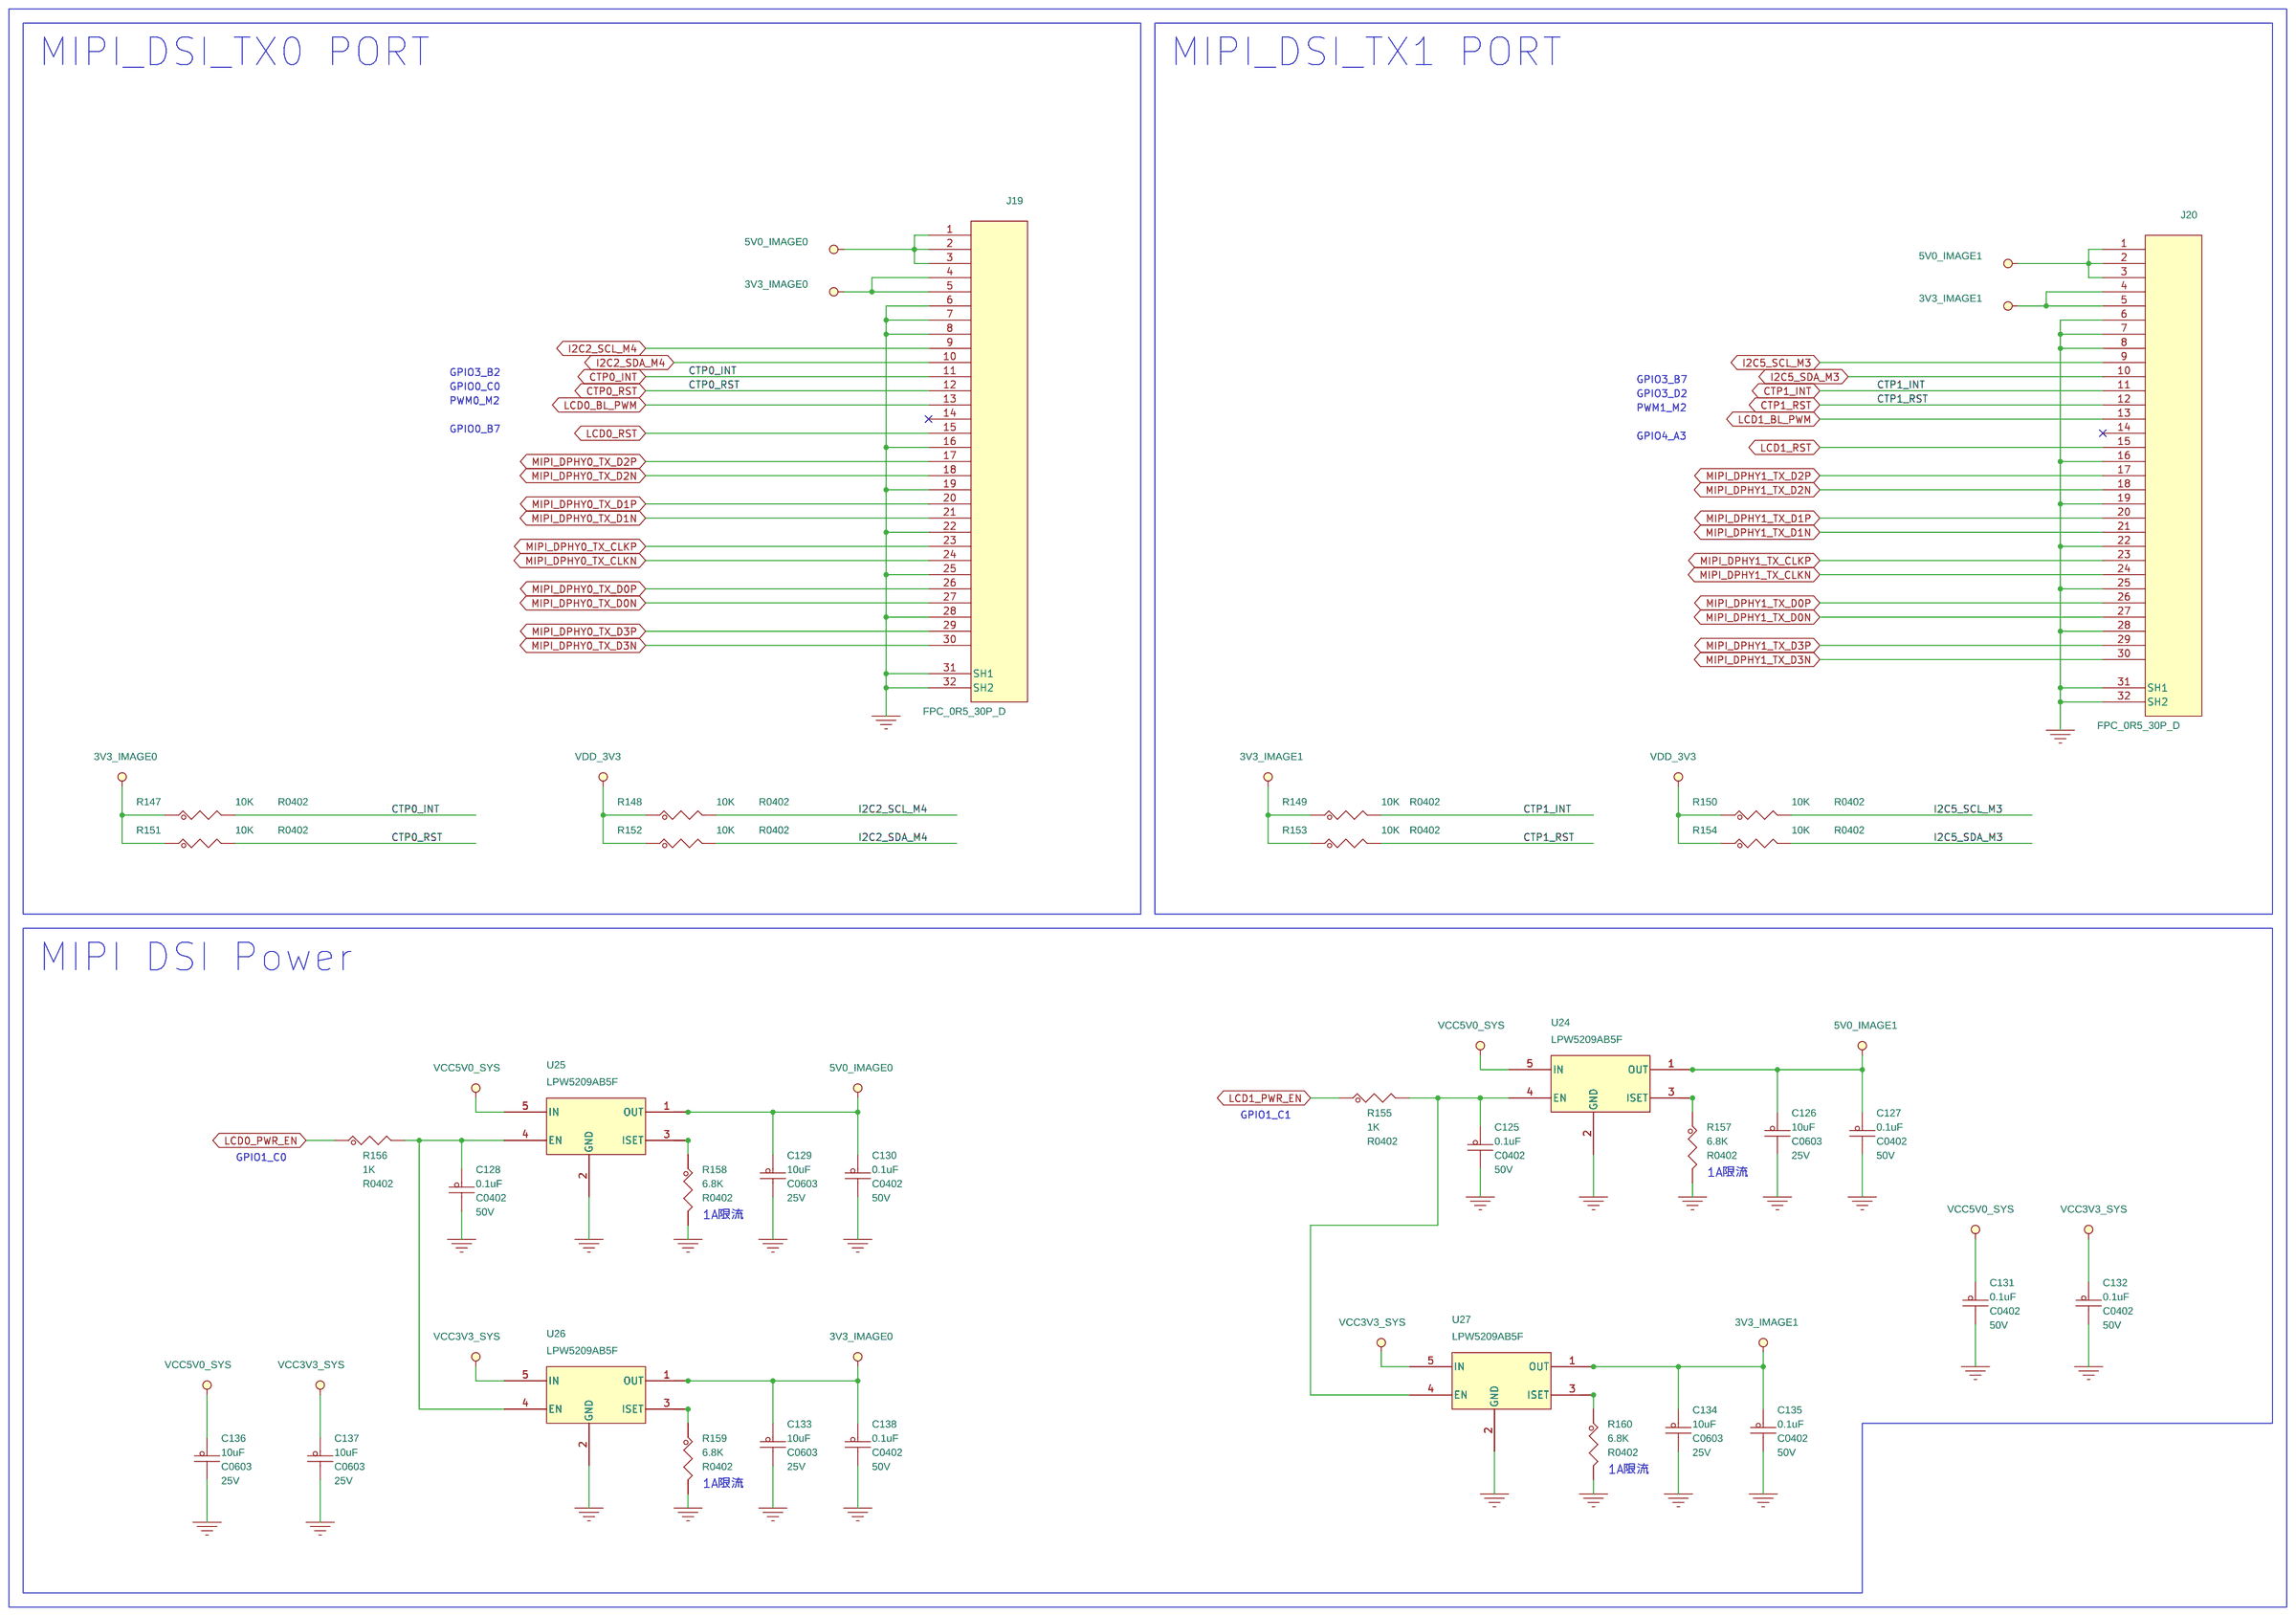
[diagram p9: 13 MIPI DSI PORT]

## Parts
sheet 05 BTB Connector
C31  0.1uF  [C0402]
C32  0.1uF  [C0402]
C33  0.1uF  [C0402]
C34  0.1uF  [C0402]
C35  0.1uF  [C0402]
C36  0.1uF  [C0402]
C37  0.1uF  [C0402]
C38  0.1uF  [C0402]
J3  DF40C-100DP-0.4V(51)  [DF40C-100DP-0P4V]
J4  DF40C-100DS-0.4V(51)  [DF40HC-100DS-0P4V]
J5  DF40C-100DP-0.4V(51)  [DF40C-100DP-0P4V]
J6  DF40C-100DS-0.4V(51)  [DF40HC-100DS-0P4V]
R23  25.5K  [R0402]
R24  10K  [R0402]
R238  0R  [R0402]
SS1  M2.5X1.5mm  [SMTSO-M2r5]
SS2  M2.5X1.5mm  [SMTSO-M2r5]
SS3  M2.5X1.5mm  [SMTSO-M2r5]
SS4  M2.5X1.5mm  [SMTSO-M2r5]
sheet 09 ETH
C70  0.1uF  [C0402]
C71  4.7uF  [C0402]
C72  4.7uF  [C0402]
C73  4.7uF  [C0402]
C74  18pF  [C0402]
C75  18pF  [C0402]
C76  0.1uF  [C0402]
C77  1nF  [C0805]
C78  0.1uF  [C0402]
C79  4.7uF  [C0402]
C80  0.1uF  [C0402]
C81  0.1uF  [C0402]
C82  4.7uF  [C0402]
C83  0.1uF  [C0402]
C84  0.1uF  [C0402]
C85  0.1uF  [C0402]
C86  4.7uF  [C0402]
C87  4.7uF  [C0402]
C88  0.1uF  [C0402]
C89  0.1uF  [C0402]
C90  0.1uF  [C0402]
J15  HY911130A  [HY911130A]
L3  2.2uH  [L2520]
R80  4.7K  [R0402]
R81  4.7K  [R0402]
R82  4.7K  [R0402]
R83  4.7K  [R0402]
R84  22R  [R0402]
R85  22R  [R0402]
R86  2.49K  [R0402]
R87  22R  [R0402]
R88  22R  [R0402]
R89  22R  [R0402]
R90  22R  [R0402]
R91  4.7K  [R0402]
R92  4.7K  [R0402]
R93  4.7K  [R0402]
R94  4.7K  [R0402]
R95  4.7K  [R0402]
R96  NC  [R0402]
R97  0R  [R0402]
R98  NC  [R0402]
R99  510R  [R0402]
R100  510R  [R0402]
R101  1M  [R0805]
R102  4.7K  [R0402]
R103  4.7K  [R0402]
R104  4.7K  [R0402]
R105  4.7K  [R0402]
R106  0R  [R0402]
R107  0R  [R0402]
R240  0R  [R0402]
U14  RTL8211F  [qfp_40p_r]
Y2  25MHz  [3225]
sheet 10 WLAN & BT
C91  10pF  [C0402]
C92  NC  [C0402]
C93  NC  [C0402]
C94  0.1uF  [C0402]
C95  10uF  [C0603]
C96  0.1uF  [C0402]
CN1  WiFi-Ant  [UFL-3]
Q6  AO3407  [SOT23]
R108  2.2R  [R0402]
R109  2.2R  [R0402]
R110  10K  [R0402]
R111  560R  [R0402]
U15  TL8821CUB  [RL-UM02WBS-8723BU]
sheet 11 USB PORT
C97  0.1uF  [C0402]
C98  0.1uF  [C0402]
C99  0.1uF  [C0402]
C100  0.1uF  [C0402]
C101  10uF  [C0402]
C102  NC  [C0402]
C103  NC  [C0402]
C104  0.1uF  [C0402]
C105  10uF  [C0402]
C106  0.1uF  [C0402]
C107  0.1uF  [C0402]
C108  0.1uF  [C0402]
C109  0.1uF  [C0402]
C110  4.7uF  [C0402]
C111  0.1uF  [C0402]
C112  0.1uF  [C0402]
J16  USB3D0_USB2D0-A-D  [USB3D0-AF-18P]  (sections A,B)
J17  USB_AF  [USB-AF]
R112  2.2R  [R0402]
R113  2.2R  [R0402]
R114  2.2R  [R0402]
R115  2.2R  [R0402]
R116  2.2R  [R0402]
R117  2.2R  [R0402]
R118  1K  [R0402]
R119  2.2R  [R0402]
R120  2.2R  [R0402]
R121  3.4K  [R0402]
R122  100K  [R0402]
R123  100K  [R0402]
R124  1K  [R0402]
R125  3.4K  [R0402]
R126  0R  [R0603]
U16  D2550-3R3  [son10_2r50x1r00x0r50]
U17  D2550-3R3  [son10_2r50x1r00x0r50]
U18  D2550-3R3  [son10_2r50x1r00x0r50]
U19  CH334F  [QFN24]
U20  LPW5209AB5F  [SOT23-5]
U21  LPW5209AB5F  [SOT23-5]
Y3  12MHz  [3225]
sheet 12 HDMI PORT
C113  0.22uF  [C0402]
C114  0.22uF  [C0402]
C115  0.22uF  [C0402]
C116  0.22uF  [C0402]
C117  0.22uF  [C0402]
C118  0.22uF  [C0402]
C119  0.22uF  [C0402]
C120  0.22uF  [C0402]
C121  1uF  [C0402]
C122  1uF  [C0402]
C123  100pF  [C0402]
C124  1uF  [C0603]
D28  1N5819W  [SOD-123]
D29  KLXES15AAA1  [ES0402]
D30  KLXES15AAA1  [ES0402]
D31  KLXES15AAA1  [ES0402]
D32  KLXES15AAA1  [ES0402]
D33  KLXES15AAA1  [ES0402]
D34  KLXES15AAA1  [ES0402]
J18  A111926-A-05-R  [con_ra_hdmi_19p_0p5_sm]
L5  330R 100MHz  [L0603]
Q7  2SK3018  [SOT23]
Q8  2SK3018  [SOT23]
Q9  2SK3018  [SOT23]
Q10  2SK3018  [SOT23]
Q11  2SK3018  [SOT23]
Q12  2SK3018  [SOT23]
Q13  2SK3018  [SOT23]
Q14  2SK3018  [SOT23]
Q15  2SK3018  [SOT23]
R127  10K  [R0402]
R128  2.2K  [R0402]
R129  10K  [R0402]
R130  1K  [R0402]
R131  2.2K  [R0402]
R132  27K  [R0402]
R133  47K  [R0402]
R134  499R  [R0402]
R135  47K  [R0402]
R136  499R  [R0402]
R137  499R  [R0402]
R138  499R  [R0402]
R139  1.2K  [R0402]
R140  499R  [R0402]
R141  499R  [R0402]
R142  47K  [R0402]
R143  499R  [R0402]
R144  499R  [R0402]
R145  1K  [R0402]
R146  10K  [R0402]
U22  D2550-3R3  [son10_2r50x1r00x0r50]
U23  D2550-3R3  [son10_2r50x1r00x0r50]
sheet 13 MIPI DSI PORT
C125  0.1uF  [C0402]
C126  10uF  [C0603]
C127  0.1uF  [C0402]
C128  0.1uF  [C0402]
C129  10uF  [C0603]
C130  0.1uF  [C0402]
C131  0.1uF  [C0402]
C132  0.1uF  [C0402]
C133  10uF  [C0603]
C134  10uF  [C0603]
C135  0.1uF  [C0402]
C136  10uF  [C0603]
C137  10uF  [C0603]
C138  0.1uF  [C0402]
J19  FPC_0R5_30P_D  [FPC-30P-0P5]
J20  FPC_0R5_30P_D  [FPC-30P-0P5]
R147  10K  [R0402]
R148  10K  [R0402]
R149  10K  [R0402]
R150  10K  [R0402]
R151  10K  [R0402]
R152  10K  [R0402]
R153  10K  [R0402]
R154  10K  [R0402]
R155  1K  [R0402]
R156  1K  [R0402]
R157  6.8K  [R0402]
R158  6.8K  [R0402]
R159  6.8K  [R0402]
R160  6.8K  [R0402]
U24  LPW5209AB5F  [SOT23-5]
U25  LPW5209AB5F  [SOT23-5]
U26  LPW5209AB5F  [SOT23-5]
U27  LPW5209AB5F  [SOT23-5]
sheet 17 TYPE C Socket
C196  10uF  [C0603]
C197  0.1uF  [C0402]
C198  0.1uF  [C0402]
C199  0.1uF  [C0402]
C200  0.1uF  [C0402]
C201  0.1uF  [C0402]
C202  0.1uF  [C0402]
C203  10uF  [C0603]
C204  10uF  [C0603]
C205  0.1uF  [C0402]
C206  0.1uF  [C0402]
C207  10uF  [C0603]
C209  220pF  [C0402]
C210  220pF  [C0402]
C211  1uF  [C0402]
D35  KLXES15AAA1  [ES0402]
D36  KLXES15AAA1  [ES0402]
J30  TYPE-C  [usb-c-smd_tyc-324g]
L7  330R 100MHz  [L0603]
R220  2.2R  [R0402]
R221  2.2R  [R0402]
R222  0R  [R0402]
R223  0R  [R0402]
R224  0R  [R0402]
R225  0R  [R0402]
R226  100K  [R0402]
R227  100K  [R0402]
R228  2M  [R0402]
R229  2M  [R0402]
R230  10K  [R0402]
R231  10K  [R0402]
R232  10K  [R0402]
R233  4.7K  [R0402]
R234  NC  [R0402]
R235  3.4K  [R0402]
R236  1K  [R0402]
R237  10K  [R0402]
U35  D2550-3R3  [son10_2r50x1r00x0r50]
U36  D2550-3R3  [son10_2r50x1r00x0r50]
U37  D2550-3R3  [son10_2r50x1r00x0r50]
U38  LPW5209AB5F  [SOT23-5]
U39  FUSB302BMPX  [WQFN14-0R50-2R5X2R5EP1R45X1R45]

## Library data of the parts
C31-C37 C94 C96 C197-C202 C205 C206 = CAP_NP: voltage: 50V; 规格: 贴片电容0.1uF 10% 50V X5R 0402; 规格编号: 0402X104K500NT; 规格书: 风华电容.pdf; 价格: 0.029826; 类别: 贴片电容0402; 品牌: 风华; 生命周期: 量产; 条码: EBF29060118
C38 C70 C76 C78 C80 C81 C83-C85 C88-C90 C97-C100 C104 C106-C109 C111 C112 C125 C127 C128 C130-C132 C135 C138 = CAP_NP: Voltage: 50V; 规格: 贴片电容0.1uF 10% 50V X5R 0402; 规格编号: 0402X104K500NT; 规格书: 风华电容.pdf; 价格: 0.029826; 类别: 贴片电容0402; 品牌: 风华; 生命周期: 量产; 条码: EBF29060118
J3 J5 = DF40C-100DP: 备注: 鲁班猫cm4; 规格: 0.4mm BTB公座2*50P 双槽 立贴式 高度1.14mm; 规格书: 广濑-DF40_Catalog.pdf; 价格: 3.39; 类别: BTB连接器; 品牌: 广濑; 生命周期: 量产; 条码: EBFCIS231113172457
J4 J6 = SGDBM-05-100P-H10: 备注: 鲁班猫cm4; 规格: 0.4mm BTB母座2*50P 双槽 立贴式 合高1.5mm; 规格书: 广濑-DF40_Catalog.pdf; 价格: 3.93; 类别: BTB连接器; 品牌: 广濑; 生命周期: 量产; 条码: EBFCIS231113172912
R23 = RES: 规格: 贴片电阻25.5K 1% 1/16W 0402; 规格编号: CQ02WGF2552TCE; 规格书: 厚声-无铅厚膜电阻.pdf; 价格: 0.006152; 类别: 贴片电阻0402; 品牌: 厚声; 生命周期: 量产; 条码: EBF29070291
R24 R110 R127 R129 R146-R154 R230-R232 R237 = RES: 规格: 贴片电阻10K 1% 1/16W 0402; 规格编号: 0402WGF1002TCE; 规格书: 厚声-无铅厚膜电阻.pdf; 价格: 0.002773; 类别: 贴片电阻0402; 品牌: 厚声; 生命周期: 量产; 条码: EBF29070046
R97 R106 R107 R222-R225 R238 R240 = RES: 规格: 贴片电阻0R 1% 1/16W 0402; 规格编号: RI0402L000FT; 规格书: 合科泰-RI系列电阻.pdf; 类别: 贴片电阻0402; 品牌: 合科泰; 生命周期: 量产; 条码: EBF29070049
SS1-SS4 = SPACER: 备注: 通用; 规格: SMT贴片螺母M2.5 台阶高度1.4MM 台阶外径：4.09MM 螺柱长度：1.5MM; 规格编号: SMTSO2515CTJ; 规格书: 雄和远景_SMTSO2530CTJ.pdf; 类别: 贴片螺母; 品牌: 雄和远景; 生命周期: 量产; 条码: EBFCIS240816170946
C71-C73 C79 C82 C86 C87 C110 = CAP_NP: Voltage: 10V; 规格: 贴片电容4.7uF 10% 10V X5R 0402; 规格编号: CC0402KRX5R6BB475; 规格书: 国巨-贴片电容.pdf; 价格: 0.059058; 类别: 贴片电容0402; 品牌: 国巨; 生命周期: 量产; 条码: EBF29060248
C74 C75 = CAP_NP: Voltage: 50V; 规格: 贴片电容18pF 5% 50V C0G 0402; 规格编号: 0402CG180J500NT; 规格书: 风华电容.pdf; 价格: 0.00515; 类别: 贴片电容0402; 品牌: 风华; 生命周期: 量产; 条码: EBF29060235
C77 = CAP_NP: voltage: 1kv; 规格: 贴片电容1nF 10% 1kV X7R 0805; 规格编号: 0805B102K102CT; 规格书: 华新科0805系列高压贴片电容.pdf; 价格: 0.083527; 类别: 贴片电容0805; 品牌: 华新科; 生命周期: 量产; 条码: EBF29060304
J15 = HY911130A: 规格: 屏蔽式以太网连接器RJ45 引脚数14 LED灯黄绿 1000M; 规格书: 汉仁_1000M_ HY911130A.pdf; 价格: 11.12; 可替代料: EBF29040053; 类别: 网口; 品牌: 汉仁; 生命周期: 量产; 条码: EBF29040053
L3 = IND: 规格: 功率电感2.2uH 2.2uH ±20% 2.06A 85mΩ; 规格编号: WIP252012P-2R2ML; 规格书: 佳邦_ WIP252012P-2R2ML.pdf; 价格: 0.129914; 类别: 贴片电感2520; 品牌: 佳邦; 生命周期: 量产; 条码: EBFCIS220927171910
R80-R83 R91-R95 R102-R105 R233 = RES: 规格: 贴片电阻4.7K 1% 1/16W 0402; 规格编号: RI0402L4701FT; 规格书: 合科泰-RI系列电阻.pdf; 类别: 贴片电阻0402; 品牌: 合科泰; 生命周期: 量产; 条码: EBF29070047
R84 R85 R87-R90 = RES: 规格: 贴片电阻22R 1% 1/16W 0402; 规格编号: RI0402L22R0FT; 规格书: 合科泰-RI系列电阻.pdf; 类别: 贴片电阻0402; 品牌: 合科泰; 生命周期: 量产; 条码: EBF29070181
R86 = RES: 规格: 贴片电阻2.49K 1% 1/16W 0402; 规格编号: 0402WGF2491TCE; 规格书: 厚声-无铅厚膜电阻.pdf; 价格: 0.004709; 类别: 贴片电阻0402; 品牌: 厚声; 生命周期: 量产; 条码: EBF29070292
R96 R98 R234 = RES: 规格: 贴片电阻NC 预留; 类别: 贴片电阻0402; 条码: EBF29070087
R99 R100 = RES: 规格: 贴片电阻510R 1% 1/16W 0402; 规格编号: 0402WGF5100TCE; 规格书: 厚声-无铅厚膜电阻.pdf; 价格: 0.003791; 类别: 贴片电阻0402; 品牌: 厚声; 生命周期: 量产; 条码: EBF29070293
R101 = RES: 规格: 贴片电阻1M 1% 1/8W 0805; 规格编号: AC0805FR-071ML; 规格书: YAGEO国巨厚膜无铅电阻.pdf; 价格: 0.02396; 类别: 贴片电阻0805; 品牌: 国巨; 生命周期: 量产; 条码: EBF29070294
U14 = RTL8211F: 规格: 以太网芯片 10M/100M/1000M 控制接口：RGMII RGMII电压：3.3V/2.5V/1.8V/1.5V; 规格编号: RTL8211F-CG; 规格书: 瑞昱_RTL8211F-CG.pdf; 价格: 15.2; 类别: 以太网芯片; 品牌: 瑞昱; 生命周期: 量产; 条码: EBF29150018
Y2 = CRYSTAL_4P: 规格: 无源晶振25MHz ±10ppm 50Ω 16pF -40℃~+85℃ 3225; 规格编号: X322525MQB4SI; 规格书: 扬兴科技-25MHZ.pdf; 价格: 0.385846; 类别: 贴片晶振 3225; 品牌: 扬兴科技; 生命周期: 量产; 条码: EBF29100005
C91 = CAP_NP: voltage: 50V; 规格: 贴片电容10pF 5% 50V C0G 0402; 规格编号: 0402CG100J500NT; 规格书: 风华电容.pdf; 价格: 0.00453; 类别: 贴片电容0402; 品牌: 风华; 生命周期: 量产; 条码: EBF29060127
C92 C93 C102 C103 = CAP_NP: 规格: 贴片电容NC 预留; 类别: 贴片电容0402; 条码: EBF29060149
C95 C196 C203 C204 C207 = CAP_NP: voltage: 25V; 规格: 贴片电容10uF 20% 25V X5R 0603; 规格编号: CL10A106MA8NRNC; 规格书: 三星电容.pdf; 价格: 0.109811; 类别: 贴片电容0603; 品牌: 三星; 生命周期: 量产; 条码: EBF29060171
CN1 = WIFI_ANT: 规格: RF同轴连接器（天线座）; 规格编号: KH-IPEX-K501-29; 规格书: 金航标-天线座.pdf; 价格: 0.247224; 类别: WiFi天线座; 品牌: 金航标; 生命周期: 量产; 条码: EBF430005
Q6 = MOSFET_P: 规格: P沟道MOS 导通电阻60mΩ 电流4.1A 3V可驱动; 规格书: 合科泰-AO3407.pdf; 价格: 0.199827; 类别: P-MOS; 品牌: 合科泰; 生命周期: 量产; 丝印: A7; 条码: EBF29280012
R108 R109 R112-R117 R119 R120 R220 R221 = RES: 规格: 贴片电阻2.2R 1% 1/16W 0402; 规格编号: 0402WGF220KTCE; 规格书: 厚声-无铅厚膜电阻.pdf; 价格: 0.003072; 类别: 贴片电阻0402; 品牌: 厚声; 生命周期: 量产; 条码: EBF29070280
R111 = RES: 规格: 贴片电阻560R 1% 1/16W 0402; 规格编号: 0402WGF5600TCE; 规格书: 厚声-无铅厚膜电阻.pdf; 价格: 0.002258; 类别: 贴片电阻0402; 品牌: 厚声; 生命周期: 量产; 条码: EBF29070272
U15 = RTL8723: 规格: RTL8821 WiFi模块 接口类型：usb 工作电压：3.3V 传输速率：150M+433M 工作频率：2.4G+5.8G 无线标准：802.11AC/B/G/n 有效通信距离：100m; 价格: 17; 类别: WiFi模块; 品牌: 创凌; 生命周期: 量产; 条码: EBF29250002
C101 C105 = CAP_NP: Voltage: 10V; 规格: 贴片电容10uF 20% 10V X5R 0402; 规格编号: CL05A106MP8NUB8; 规格书: 三星电容.pdf; 价格: 0.518415; 类别: 贴片电容0402; 品牌: 三星; 生命周期: 量产; 条码: EBF29060247
J16 = USB3D0_USB2D0-A-D: 规格: USB3.0_USB2.0母座; 规格编号: UEA1112C-UHS6-4F; 规格书: UEA1112C-UHS6-4F.pdf; 类别: USB接口; 品牌: 富士康; 生命周期: 量产; 条码: EBF29040092
J17 = USB_AF: 规格: 垂直 额定电流1.5A 母座 USB - Type A USB 2.0; 规格编号: USB-AF侧插铜; 规格书: 精拓金-USB侧插.pdf; 价格: 0.5872; 类别: USB接口; 品牌: 精拓金; 生命周期: 量产; 条码: EBF29040024
R118 R124 R130 R145 R155 R156 R236 = RES: 规格: 贴片电阻1K 1% 1/16W 0402; 规格编号: RI0402L1001FT; 规格书: 合科泰-RI系列电阻.pdf; 类别: 贴片电阻0402; 品牌: 合科泰; 生命周期: 量产; 条码: EBF29070050
R121 R125 R235 = RES: 规格: 贴片电阻3.4K 1% 1/16W 0402; 规格编号: RI0402L3401FT; 规格书: 合科泰-RI系列电阻.pdf; 类别: 贴片电阻0402; 品牌: 合科泰; 生命周期: 量产; 条码: EBF29070186
R122 R123 R226 R227 = RES: 规格: 贴片电阻100K 1% 1/16W 0402; 规格编号: RI0402L1003FT; 规格书: 合科泰-RI系列电阻.pdf; 类别: 贴片电阻0402; 品牌: 合科泰; 生命周期: 量产; 条码: EBF29070054
R126 = RES: 规格: 贴片电阻0R 1% 1/10W 0603; 规格编号: RI0603L0000FT; 规格书: 合科泰-RI系列电阻.pdf; 类别: 贴片电阻0603; 品牌: 合科泰; 生命周期: 量产; 条码: EBF29070063
U16-U18 U22 U23 U35-U37 = RCLAMP0524P: 备注: 猫5 HDMI2.1新物料; 规格: 用于 USB3.0、HDMI2.1和高速接口的四路0.13pF、3.3V、±12kV ESD 保护二极管; 规格书: 千虹_D2550-3R3.pdf; 类别: 贴片四路ESD; 品牌: 千虹; 生命周期: 量产; 丝印: 3324P; 条码: EBFCIS231110170954
U19 = CH334F: 规格: USB HUB芯片 工作电压3.3V 5V 协议类别USB2.0 支持高速(480Mbps) 全速(12Mbps)和低速(1.5Mbps)模式; 规格书: 南京沁恒_CH334F.pdf; 价格: 2.09; 类别: USB芯片; 品牌: 南京沁恒; 生命周期: 量产; 条码: EBFCIS221222095807
U20 U21 U24-U27 U38 = LPW5209AB5F: 规格: 集成电源开关 导通电阻：80mΩ 最大可设置保护电流：2.1A 输入电压：2.5V~6V 静态电流：30uA 其他功能：软启动、短路保护、热保护; 规格书: 微源半导体_LPW5209AB5F.pdf; 价格: 0.468063; 类别: 功率开关; 品牌: 微源半导体; 生命周期: 量产; 条码: EBF29280015
Y3 = CRYSTAL_4P: 规格: 无源晶振12MHz ±10ppm 80Ω 20pF -40℃~+85℃ 3225; 规格编号: X322512MSB4SI; 规格书: 扬兴科技-贴片晶振.pdf; 价格: 0.327763; 可替代料: EBF29100013; 类别: 贴片晶振 3225; 品牌: 扬兴科技; 生命周期: 量产; 条码: EBF29100013
C113-C120 = CAP_NP: voltage: 25V; 备注: 新增0402物料; 规格: 贴片电容0.22uF 20% 25V X7R 0402; 规格编号: TCC0402X7R224K250AT; 规格书: CCTC_TCC0402X5R105K6R3AT; 价格: 0.0073; 类别: 贴片电容0402; 品牌: CCTC; 生命周期: 量产; 条码: EBFCIS241220094109
C121 C122 C211 = CAP_NP: voltage: 10V; 规格: 贴片电容1uF 10% 10V X5R 0402; 规格编号: 0402X105K100NT; 规格书: 风华电容.pdf; 价格: 0.01191; 类别: 贴片电容0402; 品牌: 风华; 生命周期: 量产; 条码: EBF29060121
C123 = CAP_NP: voltage: 50V; 规格: 贴片电容100pF 5% 50V C0G 0402; 规格编号: GRT1555C1H101JA; 规格书: 村田040系列贴片电容.pdf; 价格: 0.034837; 类别: 贴片电容0402; 品牌: 村田; 生命周期: 量产; 条码: EBF29060302
C124 = CAP_NP: Voltage: 50V; 规格: 贴片电容1uF 10% 50V X7R 0603; 规格编号: 0603B105K500NT; 规格书: 风华电容.pdf; 价格: 0.099678; 类别: 贴片电容0603; 品牌: 风华; 生命周期: 量产; 条码: EBF29060168
D28 = DIODE_SCHTKY: 规格: 肖特基二极管 直流反向耐压40V 平均整流电流1A 正向压降0.6V@1A SOD-123; 规格书: 1N5819W.pdf; 价格: 0.175675; 类别: 贴片肖特基二极管; 品牌: 台湾迪嘉; 生命周期: 量产; 丝印: SL; 条码: EBF29140016
D29-D36 = DIODE_BI-DIR_TRIG: 规格: 用于 USB3.0、HDMI 0.5pF、5V、±15kV ESD 保护二极管; 规格书: KLXES15AAA1.pdf; 价格: 0.09719; 类别: 贴片ESD; 品牌: 永裕泰; 生命周期: 量产; 条码: EBF29140063
J18 = A111926-A-05-R: 规格: HDMI_19P母座 额定电压40V 接触电阻10毫欧 卧贴; 规格书: TECONN(泰康)_HDMI.pdf; 价格: 1.6342; 类别: HDMI连接器; 品牌: 泰康; 生命周期: 量产; 条码: EBF29040046
L5 L7 = BEAD: 规格: 磁珠330Ω @100MHz 额定电流1.7A 直流电阻80mΩ; 规格编号: MPZ1608S331ATA00; 规格书: TDK-MPZ1608S331ATA00.pdf; 类别: 贴片磁珠0603; 品牌: TDK; 生命周期: 量产; 条码: EBF29050003
Q7-Q15 = 2SK3018: 规格: N沟道MOS 导通电阻8Ω 电流10mA 0.8V可驱动; 规格书: 长电科技-2SK3018.pdf; 价格: 0.120725; 类别: N-MOS; 品牌: 江苏长电; 生命周期: 量产; 丝印: KN; 条码: EBF29280009
R128 R131 = RES: 规格: 贴片电阻2.2K 1% 1/16W 0402; 规格编号: RI0402L2201FT; 规格书: 合科泰-RI系列电阻.pdf; 类别: 贴片电阻0402; 品牌: 合科泰; 生命周期: 量产; 条码: EBF29070051
R132 = RES: 规格: 贴片电阻27K 1% 1/16W 0402; 规格编号: AC0402FR-0727KL; 规格书: YAGEO国巨厚膜无铅电阻.pdf; 价格: 0.007054; 类别: 贴片电阻0402; 品牌: 国巨; 生命周期: 量产; 条码: EBF29070003
R133 R135 R142 = RES: 规格: 贴片电阻47K 1% 1/16W 0402; 规格编号: 0402WGF4702TCE; 规格书: 厚声-无铅厚膜电阻.pdf; 类别: 贴片电阻0402; 品牌: 厚声; 生命周期: 量产; 条码: EBF29070247
R134 R136-R138 R140 R141 R143 R144 = RES: 规格: 贴片电阻499R 1% 1/16W 0402; 规格编号: 0402WGF4990TCE; 规格书: 厚声-无铅厚膜电阻.pdf; 价格: 0.003791; 类别: 贴片电阻0402; 品牌: 厚声; 生命周期: 量产; 条码: EBF29070287
R139 = RES: 规格: 贴片电阻1.2K 1% 1/16W 0402; 规格编号: 0402WGF1201TCE; 规格书: 厚声-无铅厚膜电阻.pdf; 价格: 0.001447; 类别: 贴片电阻0402; 品牌: 厚声; 生命周期: 量产; 条码: EBFCIS221112112140
C126 C129 C133 C134 C136 C137 = CAP_NP: Voltage: 25V; 规格: 贴片电容10uF 20% 25V X5R 0603; 规格编号: CL10A106MA8NRNC; 规格书: 三星电容.pdf; 价格: 0.109811; 类别: 贴片电容0603; 品牌: 三星; 生命周期: 量产; 条码: EBF29060171
J19 J20 = FPC-30P: 规格: FPC连接器 针脚数30 间距0.5mm 高度2.0mm 下接 卧贴 翻盖式; 规格编号: FPC-05F-30PH20; 规格书: FPC-05F-NPH20.pdf; 类别: FPC连接器; 品牌: 讯普; 生命周期: 量产; 条码: EBF29040079
R157-R160 = RES: 规格: 贴片电阻6.8K 1% 1/16W 0402; 规格编号: RI0402L6801FT; 规格书: 合科泰-RI系列电阻.pdf; 类别: 贴片电阻0402; 品牌: 合科泰; 生命周期: 量产; 条码: EBF29070052
C209 C210 = CAP_NP: voltage: 50V; 规格: 贴片电容220pF 10% 50V X7R 0402; 规格编号: 0402B221K500NT; 规格书: 风华电容.pdf; 价格: 0.00358; 类别: 贴片电容0402; 品牌: 风华; 条码: EBFCIS221112143723
J30 = TYPE-C-24P: 规格: Type-C母座 24P USB-3.1 插座 4固定脚 双向; 规格编号: TYC-324G; 规格书: 讯普_TYC-324G.pdf; 类别: USB接口; 品牌: 讯普; 条码: EBFCIS220922094113
R228 R229 = RES: 规格: 贴片电阻2M 1% 1/16W 0402; 规格编号: 0402WGF2004TCE; 规格书: 厚声-无铅厚膜电阻.pdf; 价格: 0.002023; 类别: 贴片电阻0402; 品牌: 厚声; 生命周期: 量产; 条码: EBFCIS221112151157
U39 = FUSB302BMPX: 规格: 可编程USB Type-C控制器 支持USB Type-C检测 带PD 可实现高达 100 W 的电源和角色互换; 规格书: 安森美_FUSB302BMPX.pdf; 价格: 3.8016; 类别: USB芯片; 品牌: 安森美; 生命周期: 量产; 条码: EBFCIS221116112239

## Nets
1V05_AVDD_PHY: C83.1 C84.1 C85.1 C86.1 R107.2 U14.3(AVDD10_2) U14.8(AVDD10_1) U14.38(AVDD10)
1V05_DVDD_PHY: C79.1 C80.1 C81.1 C82.1 R106.1 U14.21(DVDD10)
1V05_PHY: C72.1 C73.1 L3.2 R106.2 R107.1
3V3_DVDD_PHY: C70.1 C71.1 C87.1 C88.1 C89.1 R80.1 R81.1 R82.1 R93.1 R94.1 R95.1 R104.2 R105.1 R240.1 U14.11(AVDD33_1) U14.28(DVDD_RG) U14.29(DVDD33) U14.40(AVDD33)
3V3_IMAGE0: C133.1 C138.1 J19.4 J19.5 R147.1 R151.1 U26.1(OUT)
3V3_IMAGE1: C134.1 C135.1 J20.4 J20.5 R149.1 R153.1 U27.1(OUT)
3V3_WLAN: C95.1 C96.1 Q6.3(DRAIN) U15.8(VCC3V3)
5V0_IMAGE0: C129.1 C130.1 J19.1 J19.2 J19.3 U25.1(OUT)
5V0_IMAGE1: C126.1 C127.1 J20.1 J20.2 J20.3 U24.1(OUT)
GND: C31.2 C32.2 C33.2 C34.2 C35.2 C36.2 C37.2 C38.2 C70.2 C71.2 C72.2 C73.2 C74.2 C75.2 C76.2 C77.2 C78.2 C79.2 C80.2 C81.2 C82.2 C83.2 C84.2 C85.2 C86.2 C87.2 C88.2 C89.2 C90.2 C92.2 C93.2 C95.2 C96.2 C99.2 C100.2 C101.2 C102.1 C103.2 C104.2 C105.2 C106.2 C107.2 C108.2 C109.2 C110.2 C111.2 C112.2 C124.2 C125.2 C126.2 C127.2 C128.2 C129.2 C130.2 C131.2 C132.2 C133.2 C134.2 C135.2 C136.2 C137.2 C138.2 C196.2 C203.2 C204.2 C205.2 C206.2 C207.2 C209.2 C210.2 C211.2 CN1.2 CN1.3 D29.1 D30.1 D31.1 D32.1 D33.1 D34.1 D35.2 D36.2 J3.7 J3.8 J3.9 J3.10 J3.11 J3.12 J3.23 J3.29 J3.32 J3.38 J3.48 J3.51 J3.54 J3.64 J3.65 J3.68 J3.81 J3.82 J3.99 J3.100 J3.101(SH1) J3.102(SH2) J3.103(SH3) J3.104(SH4) J4.1 J4.2 J4.10 J4.11 J4.17 J4.18 J4.26 J4.27 J4.32 J4.37 J4.38 J4.43 J4.53 J4.54 J4.62 J4.72 J4.75 J4.82 J4.88 J4.94 J4.97 J4.99 J4.100 J5.1 J5.2 J5.11 J5.12 J5.17 J5.18 J5.27 J5.28 J5.33 J5.34 J5.44 J5.51 J5.52 J5.57 J5.58 J5.73 J5.76 J5.79 J5.82 J5.91 J5.100 J5.101(SH1) J5.102(SH2) J5.103(SH3) J5.104(SH4) J6.1 J6.2 J6.8 J6.14 J6.19 J6.20 J6.25 J6.30 J6.40 J6.43 J6.49 J6.67 J6.68 J6.78 J6.83 J6.84 J6.90 J6.96 J6.97 J6.98 J6.99 J6.100 J15.10(CHS) J16.4(GND1) J16.7(GND2) J16.13(GND1) J16.16(NC3) J16.19(SH1) J16.20(SH2) J16.21(SH1) J16.22(SH2) J17.4(GND) J17.5(SH1) J17.6(SH2) J17.7(SH3) J17.8(SH4) J18.2(D2GND) J18.5(D1GND) J18.8(D0GND) J18.11(CKGND) J18.17(DDCGND) J19.6 J19.7 J19.8 J19.16 J19.19 J19.22 J19.25 J19.28 J19.31(SH1) J19.32(SH2) J20.6 J20.7 J20.8 J20.16 J20.19 J20.22 J20.25 J20.28 J20.31(SH1) J20.32(SH2) J30.A1(GND1) J30.A12(GND2) J30.B1(GND3) J30.B12(GND4) L5.2 L7.2 Q10.2(SOURCE) Q11.2(SOURCE) Q12.2(SOURCE) Q13.2(SOURCE) Q14.2(SOURCE) Q15.2(SOURCE) R24.2 R83.2 R86.2 R91.2 R92.2 R98.2 R99.2 R100.2 R101.2 R102.2 R103.2 R121.2 R125.2 R142.2 R146.2 R157.2 R158.2 R159.2 R160.2 R228.2 R229.2 R234.1 R235.2 R237.2 SS1.1(NC) SS2.1(NC) SS3.1(NC) SS4.1(NC) U14.41(GND) U15.1(GND) U15.5(GND) U16.3(GND1) U16.8(GND2) U17.3(GND1) U17.8(GND2) U18.3(GND1) U18.8(GND2) U19.25(VSS) U20.2(GND) U21.2(GND) U22.3(GND1) U22.8(GND2) U23.3(GND1) U23.8(GND2) U24.2(GND) U25.2(GND) U26.2(GND) U27.2(GND) U35.3(GND1) U35.8(GND2) U36.3(GND1) U36.8(GND2) U37.3(GND1) U37.8(GND2) U38.2(GND) U39.8(GND1) U39.9(GND2) U39.15(EPAD) Y2.2(GND1) Y2.4(GND2) Y3.2(GND1) Y3.4(GND2) ; also on sheet 11 12 13 14 15 16 17
VBUS_TYPEC: C196.1 C206.1 C207.1 J30.A4(VBUS1) J30.A9(VBUS2) J30.B4(VBUS3) J30.B9(VBUS4) U38.1(OUT) U39.2(VBUS)
VCC3V3_SYS: C132.1 C137.1 U26.5(IN) U27.5(IN) ; also on sheet 16
VCC5V0_SYS: C31.1 C32.1 C107.1 C108.1 C131.1 C136.1 C203.1 C204.1 C205.1 J3.1 J3.2 J3.3 J3.4 J3.5 J3.6 R238.1 U20.5(IN) U21.5(IN) U24.5(IN) U25.5(IN) U38.5(IN) U39.12(VCONN1) U39.13(VCONN2) ; also on sheet 11 13 16 17
VCC_1V8_S0: J3.21 J3.22 ; also on sheet 13
VCC_1V8_S3: C35.1 J3.19 J3.20 ; also on sheet 14
VCC_3V3_S3: C36.1 C37.1 C211.1 J3.13 J3.14 R230.1 R231.1 R232.1 R233.1 U39.3(VDD1) U39.4(VDD2) ; also on sheet 14 16 17
VCCA_1V8_S0: C34.1 J3.17 J3.18 R23.1 ; also on sheet 13 17
VCCA_3V3_S0: C33.1 J3.15 J3.16 ; also on sheet 13
VDD_3V3: C90.1 C94.1 C109.1 Q6.2(SOURCE) Q7.1(GATE) R110.1 R126.1 R127.1 R129.1 R130.1 R132.1 R133.1 R135.1 R148.1 R150.1 R152.1 R154.1 R240.2 ; also on sheet 11 14 15 16 17
VDD_5V: D28.2 Q9.1(GATE) ; also on sheet 15 16
B_DM1: J16.2(D-) R116.1 U16.4(D2+) U16.7(NC3)
B_DM2: J16.11(D-) R112.1 U16.1(D1+) U16.10(NC1)
B_DM3: J17.2(D-) R114.1 U18.2(D1-) U18.9(NC2)
B_DP1: J16.3(D+) R117.1 U16.5(D2-) U16.6(NC4)
B_DP2: J16.12(D+) R113.1 U16.2(D1-) U16.9(NC2)
B_DP3: J17.3(D+) R115.1 U18.1(D1+) U18.10(NC1)
BD_CH3: C38.1 J4.48 R23.2 R24.1
CAM0/1_PWR_EN: J5.69 ; also on sheet 11
CAM0_nRST: J4.6 ; also on sheet 11
CAM0_PWDN: J4.4 ; also on sheet 11
CAM1_nRST: J4.12 ; also on sheet 11
CAM1_PWDN: J4.8 ; also on sheet 11
CAM2/3_PWR_EN: J5.71 ; also on sheet 11
CAM2_nRST: J4.16 ; also on sheet 11
CAM2_PWDN: J4.14 ; also on sheet 11
CAM3_nRST: J4.22 ; also on sheet 11
CAM3_PWDN: J4.20 ; also on sheet 11
CAN1_RX_M1: J4.30 ; also on sheet 15
CAN1_TX_M1: J4.28 ; also on sheet 15
CAN2_RX_M0: J4.36 ; also on sheet 15
CAN2_TX_M0: J4.34 ; also on sheet 15
CTP0_INT: J6.44 J19.11 R147.2
CTP0_RST: J5.62 J19.12 R151.2
CTP1_INT: J6.46 J20.11 R149.2
CTP1_RST: J6.70 J20.12 R153.2
DEBUG_RX: J5.78 ; also on sheet 17
DEBUG_TX: J5.80 ; also on sheet 17
EARPHONE_CTL: J5.72 ; also on sheet 13
EXT_PWR_EN: J3.30 ; also on sheet 16 17
FAN_PWM: J5.63 ; also on sheet 16
FUSB302_INT: J5.68 R232.2 U39.5(~{INT})
GMAC1_INT: J6.48 R96.1
GMAC1_MCLK_INOUT: J3.67 R97.1 R98.1
GMAC1_MDC: J3.95 R93.2 U14.13(MDC)
GMAC1_MDIO: J3.97 R94.2 U14.14(MDIO)
GMAC1_RSTn: C78.1 J6.50 R105.2 U14.12(PHYRSTB)
GMAC1_RXCLK: J3.85 R83.1 R89.1
GMAC1_RXD0: J3.87 R80.2 R84.1
GMAC1_RXD1: J3.89 R81.2 R85.1
GMAC1_RXD2: J3.91 R87.1 R91.1
GMAC1_RXD3: J3.93 R82.2 R88.1
GMAC1_RXDV_CRS: J3.83 R90.1 R92.1
GMAC1_TXCLK: J3.69 U14.20(TXC)
GMAC1_TXD0: J3.73 U14.18(TXD0)
GMAC1_TXD1: J3.75 U14.17(TXD1)
GMAC1_TXD2: J3.77 U14.16(TXD2)
GMAC1_TXD3: J3.79 U14.15(TXD3)
GMAC1_TXEN: J3.71 U14.19(TXCTL)
HDMI0_TX_ON: J6.89 R145.1
HDMI_5V: C124.1 D28.1 D34.2 J18.18(+5V) R128.1 R131.1
HDMI_eARC+: C121.2 D32.2 J18.14(Utility)
HDMI_eARC-: C122.2 D29.2 J18.19(HPD) R139.2
HDMI_TX0_CEC_M0: J4.60 Q9.2(SOURCE) R132.2
HDMI_TX0_D0N: C118.1 J6.37
HDMI_TX0_D0P: C117.1 J6.35
HDMI_TX0_D1N: C115.1 J6.33
HDMI_TX0_D1P: C114.1 J6.31
HDMI_TX0_D2N: C116.1 J6.29
HDMI_TX0_D2P: C113.1 J6.27
HDMI_TX0_D3N: C120.1 J6.41
HDMI_TX0_D3P: C119.1 J6.39
HDMI_TX0_HPD_M0: J6.92 Q10.3(DRAIN) R133.2
HDMI_TX0_SBDN: C122.1 J6.47
HDMI_TX0_SBDP: C121.1 J6.45
HDMI_TX0_SCL_M0: J4.56 Q7.2(SOURCE) R127.2
HDMI_TX0_SDA_M0: C123.2 J4.58 Q8.2(SOURCE) R129.2
HP_PLUG_IN_DET: J5.46 ; also on sheet 13
HUB_3V3: C110.1 C111.1 C112.1 R122.1 R123.1 R126.2 U19.1(OVCUR#) U19.20(VDD3V3)
HUB_DM1: R116.2 U19.11(DM1)
HUB_DM2: R112.2 U19.9(DM2)
HUB_DM3: R114.2 U19.7(DM3)
HUB_DM4: U18.5(D2-) U18.6(NC4) U19.5(DM4) ; also on sheet 12
HUB_DP1: R117.2 U19.12(DP1)
HUB_DP2: R113.2 U19.10(DP2)
HUB_DP3: R115.2 U19.8(DP3)
HUB_DP4: U18.4(D2+) U18.7(NC3) U19.6(DP4) ; also on sheet 12
I2C0_SCL_M2: J5.84 ; also on sheet 14
I2C0_SDA_M2: J5.86 ; also on sheet 14
I2C1_SCL_M2: J5.88 R230.2 U39.6(SCL) ; also on sheet 11
I2C1_SDA_M2: J5.90 R231.2 U39.7(SDA) ; also on sheet 11
I2C2_SCL_M4: J5.54 J19.9 R148.2 ; also on sheet 11
I2C2_SDA_M4: J5.56 J19.10 R152.2 ; also on sheet 11
I2C5_SCL_M3: J5.92 J20.9 R150.2 ; also on sheet 11
I2C5_SDA_M3: J5.94 J20.10 R154.2 ; also on sheet 11
I2C7_SCL_M0_CODEC: J5.77 ; also on sheet 13
I2C7_SDA_M0_CODEC: J5.75 ; also on sheet 13
I2C8_SCL_M2: J5.96 ; also on sheet 11
I2C8_SDA_M2: J5.98 ; also on sheet 11
I2S0_LRCK: J5.85 ; also on sheet 13
I2S0_MCLK: J5.81 ; also on sheet 13
I2S0_SCLK: J5.83 ; also on sheet 13
I2S0_SDI0: J5.89 ; also on sheet 13
I2S0_SDO0: J5.87 ; also on sheet 13
LCD0_BL_PWM: J6.85 J19.13
LCD0_PWR_EN: J5.59 R156.1
LCD0_RST: J5.66 J19.15
LCD1_BL_PWM: J6.87 J20.13
LCD1_PWR_EN: J5.61 R155.1
LCD1_RST: J6.60 J20.15
MDIN0_PHY: J15.3(TD1-) U14.2(MDIN0)
MDIN1_PHY: J15.7(RD1-) U14.5(MDIN1)
MDIN2_PHY: J15.6(TD2-) U14.7(MDIN2)
MDIN3_PHY: J15.9(RD2-) U14.10(MDIN3)
MDIP0_PHY: J15.2(TD1+) U14.1(MDIP0)
MDIP1_PHY: J15.4(RD1+) U14.4(MDIP1)
MDIP2_PHY: J15.5(TD2+) U14.6(MDIP2)
MDIP3_PHY: J15.8(RD2+) U14.9(MDIP3)
MINIPCIE_nWDISABLE: J6.42 ; also on sheet 12
MINIPCIE_PWR_EN: J5.74 ; also on sheet 12
MIPI_CSI0_RX_CLK0N: J3.52 ; also on sheet 11
MIPI_CSI0_RX_CLK0P: J3.50 ; also on sheet 11
MIPI_CSI0_RX_CLK1N: J3.36 ; also on sheet 11
MIPI_CSI0_RX_CLK1P: J3.34 ; also on sheet 11
MIPI_CSI0_RX_D0N: J3.62 ; also on sheet 11
MIPI_CSI0_RX_D0P: J3.60 ; also on sheet 11
MIPI_CSI0_RX_D1N: J3.58 ; also on sheet 11
MIPI_CSI0_RX_D1P: J3.56 ; also on sheet 11
MIPI_CSI0_RX_D2N: J3.46 ; also on sheet 11
MIPI_CSI0_RX_D2P: J3.44 ; also on sheet 11
MIPI_CSI0_RX_D3N: J3.42 ; also on sheet 11
MIPI_CSI0_RX_D3P: J3.40 ; also on sheet 11
MIPI_DPHY0_RX_CLKN: J4.15 ; also on sheet 11
MIPI_DPHY0_RX_CLKP: J4.13 ; also on sheet 11
MIPI_DPHY0_RX_D0N: J4.25 ; also on sheet 11
MIPI_DPHY0_RX_D0P: J4.23 ; also on sheet 11
MIPI_DPHY0_RX_D1N: J4.21 ; also on sheet 11
MIPI_DPHY0_RX_D1P: J4.19 ; also on sheet 11
MIPI_DPHY0_RX_D2N: J4.9 ; also on sheet 11
MIPI_DPHY0_RX_D2P: J4.7 ; also on sheet 11
MIPI_DPHY0_RX_D3N: J4.5 ; also on sheet 11
MIPI_DPHY0_RX_D3P: J4.3 ; also on sheet 11
MIPI_DPHY0_TX_CLKN: J4.41 J19.24
MIPI_DPHY0_TX_CLKP: J4.39 J19.23
MIPI_DPHY0_TX_D0N: J4.51 J19.27
MIPI_DPHY0_TX_D0P: J4.49 J19.26
MIPI_DPHY0_TX_D1N: J4.47 J19.21
MIPI_DPHY0_TX_D1P: J4.45 J19.20
MIPI_DPHY0_TX_D2N: J4.35 J19.18
MIPI_DPHY0_TX_D2P: J4.33 J19.17
MIPI_DPHY0_TX_D3N: J4.31 J19.30
MIPI_DPHY0_TX_D3P: J4.29 J19.29
MIPI_DPHY1_RX_CLKN: J4.87 ; also on sheet 11
MIPI_DPHY1_RX_CLKP: J4.85 ; also on sheet 11
MIPI_DPHY1_RX_D0N: J4.95 ; also on sheet 11
MIPI_DPHY1_RX_D0P: J4.93 ; also on sheet 11
MIPI_DPHY1_RX_D1N: J4.91 ; also on sheet 11
MIPI_DPHY1_RX_D1P: J4.89 ; also on sheet 11
MIPI_DPHY1_RX_D2N: J4.83 ; also on sheet 11
MIPI_DPHY1_RX_D2P: J4.81 ; also on sheet 11
MIPI_DPHY1_RX_D3N: J4.79 ; also on sheet 11
MIPI_DPHY1_RX_D3P: J4.77 ; also on sheet 11
MIPI_DPHY1_TX_CLKN: J4.65 J20.24
MIPI_DPHY1_TX_CLKP: J4.63 J20.23
MIPI_DPHY1_TX_D0N: J4.73 J20.27
MIPI_DPHY1_TX_D0P: J4.71 J20.26
MIPI_DPHY1_TX_D1N: J4.69 J20.21
MIPI_DPHY1_TX_D1P: J4.67 J20.20
MIPI_DPHY1_TX_D2N: J4.61 J20.18
MIPI_DPHY1_TX_D2P: J4.59 J20.17
MIPI_DPHY1_TX_D3N: J4.57 J20.30
MIPI_DPHY1_TX_D3P: J4.55 J20.29
OTG_DM: D36.1 J30.A7(DN1) J30.B7(DN2) R221.1
OTG_DP: D35.1 J30.A6(DP1) J30.B6(DP2) R220.1
PCIE20_0_CLKN: J5.16 ; also on sheet 12
PCIE20_0_CLKP: J5.14 ; also on sheet 12
PCIE20_0_RXN: J5.6 ; also on sheet 12
PCIE20_0_RXP: J5.4 ; also on sheet 12
PCIE20_0_TXN: J5.10 ; also on sheet 12
PCIE20_0_TXP: J5.8 ; also on sheet 12
PCIE20x1_2_CLKREQn_M0: J6.54 ; also on sheet 12
PCIE20x1_2_PERSTn_M0: J6.74 ; also on sheet 12
PCIE20x1_2_WAKEn_M0: J6.56 ; also on sheet 12
PHY1_CLKOUT125: R97.2 U14.35(CLKOUT)
PHY1_LED1: J15.14(YELA) R103.1 U14.33(LED1)
PHY1_LED2: J15.11(GRLA) R102.1 U14.34(LED2)
PWM7_IR_M0: J5.70 ; also on sheet 17
PWRON_EN: J3.24 R238.2
PWRON_KEY: J3.28 ; also on sheet 17
RESET_KEY: J3.26 ; also on sheet 17
RTC_32K_IN: J5.50 ; also on sheet 14
RTC_INT: J5.48 ; also on sheet 14
SARADC_BOOT: J4.52 ; also on sheet 17
SARADC_IN1/REC: J4.50 ; also on sheet 17
SARADC_IN4: J4.46 ; also on sheet 17
SARADC_IN5: J4.44 ; also on sheet 17
SBU_1: C201.1 J30.A8(SUB1) R226.1 R229.1 U37.1(D1+) U37.10(NC1)
SBU_2: C202.1 J30.B8(SUB2) R227.1 R228.1 U37.2(D1-) U37.9(NC2)
SDMMC_CLK: J6.77 ; also on sheet 14
SDMMC_CMD: J6.79 ; also on sheet 14
SDMMC_D0: J6.69 ; also on sheet 14
SDMMC_D1: J6.71 ; also on sheet 14
SDMMC_D2: J6.73 ; also on sheet 14
SDMMC_D3: J6.75 ; also on sheet 14
SDMMC_DET: J6.81 ; also on sheet 14
SPK_CTRL: J4.24 ; also on sheet 13
SS_TXN: C97.1 J16.8(TX-) U17.4(D2+) U17.7(NC3)
SS_TXP: C98.1 J16.9(TX+) U17.5(D2-) U17.6(NC4)
SSRX_1N: J30.B10(SSRXN1) R223.1 U35.5(D2-) U35.6(NC4)
SSRX_1P: J30.B11(SSRXP1) R222.1 U35.4(D2+) U35.7(NC3)
SSRX_2N: J30.A10(SSRXN2) R225.1 U36.5(D2-) U36.6(NC4)
SSRX_2P: J30.A11(SSRXP2) R224.1 U36.4(D2+) U36.7(NC3)
SSTX_1N: C198.1 J30.A3(SSTXN1) U35.1(D1+) U35.10(NC1)
SSTX_1P: C197.1 J30.A2(SSTXP1) U35.2(D1-) U35.9(NC2)
SSTX_2N: C200.1 J30.B3(SSTXN2) U36.1(D1+) U36.10(NC1)
SSTX_2P: C199.1 J30.B2(SSTXP2) U36.2(D1-) U36.9(NC2)
SYS_LED: J5.65 ; also on sheet 17
TX_CEC_PORT: D33.2 J18.13(CEC) Q9.3(DRAIN)
TX_D0N_PORT: C118.2 J18.9(D0-) R136.1 U23.4(D2+) U23.7(NC3)
TX_D0P_PORT: C117.2 J18.7(D0+) R134.1 U23.5(D2-) U23.6(NC4)
TX_D1N_PORT: C115.2 J18.6(D1-) R138.1 U22.1(D1+) U22.10(NC1)
TX_D1P_PORT: C114.2 J18.4(D1+) R137.1 U22.2(D1-) U22.9(NC2)
TX_D2N_PORT: C116.2 J18.3(D2-) R141.1 U22.4(D2+) U22.7(NC3)
TX_D2P_PORT: C113.2 J18.1(D2+) R140.1 U22.5(D2-) U22.6(NC4)
TX_D3N_PORT: C120.2 J18.12(CK-) R144.1 U23.1(D1+) U23.10(NC1)
TX_D3P_PORT: C119.2 J18.10(CK+) R143.1 U23.2(D1-) U23.9(NC2)
TX_ON: Q12.1(GATE) Q13.1(GATE) Q14.1(GATE) Q15.1(GATE) R145.2 R146.1
TX_SCL_PORT: D31.2 J18.15(SCL) Q7.3(DRAIN) R128.2
TX_SDA_PORT: D30.2 J18.16(SDA) Q8.3(DRAIN) R131.2
TYPE_C_PWR_EN: J6.66 R236.1
TYPEC0_OTG_DM: J4.98 R221.2
TYPEC0_OTG_DP: J4.96 R220.2
TYPEC0_OTG_VBUSDET: J4.92 R233.2
TYPEC0_SBU1/DP0_AUXP: C201.2 J4.84
TYPEC0_SBU1_DC: J6.93 R226.2
TYPEC0_SBU2/DP0_AUXN: C202.2 J4.86
TYPEC0_SBU2_DC: J6.95 R227.2
TYPEC0_SSRX1N/DP0_TX0N: J4.80 R223.2
TYPEC0_SSRX1P/DP0_TX0P: J4.78 R222.2
TYPEC0_SSRX2N/DP0_TX2N: J4.70 R225.2
TYPEC0_SSRX2P/DP0_TX2P: J4.68 R224.2
TYPEC0_SSTX1N/DP0_TX1N: C198.2 J4.76
TYPEC0_SSTX1P/DP0_TX1P: C197.2 J4.74
TYPEC0_SSTX2N/DP0_TX3N: C200.2 J4.66
TYPEC0_SSTX2P/DP0_TX3P: C199.2 J4.64
TYPEC0_USB20_OTG_ID: J4.90 R234.2
TYPEC_CC1: C210.1 J30.A5(CC1) U37.4(D2+) U37.7(NC3) U39.10(CC1_1) U39.11(CC1_2)
TYPEC_CC2: C209.1 J30.B5(CC2) U37.5(D2-) U37.6(NC4) U39.1(CC2) U39.14(CC2_2)
UART0_RX_M0: J5.60 ; also on sheet 14
UART0_TX_M0: J5.64 ; also on sheet 14
UART4_DIR: J6.72 ; also on sheet 15
UART4_RX_M2: J5.97 ; also on sheet 15
UART4_TX_M2: J5.99 ; also on sheet 15
UART7_DIR: J6.94 ; also on sheet 15
UART7_RX_M2: J5.93 ; also on sheet 15
UART7_TX_M2: J5.95 ; also on sheet 15
UART9_RX_M2: J6.76 ; also on sheet 14
UART9_TX_M2: J6.58 ; also on sheet 14
USB20_HOST0_DM: J6.88 R120.2
USB20_HOST0_DP: J6.86 R119.2
USB20_HOST1_DM: J6.82 R109.1
USB20_HOST1_DP: J6.80 R108.1
USB20_PWR_EN: J6.64 R124.1
USB20_VBUS: C105.1 C106.1 J16.10(VBUS) J17.1(VCC) U21.1(OUT)
USB30_PWR_EN: J6.62 R118.1
USB30_SSRXN: J5.21 J16.5(RX-) U17.1(D1+) U17.10(NC1)
USB30_SSRXP: J5.19 J16.6(RX+) U17.2(D1-) U17.9(NC2)
USB30_SSTXN: C97.2 J5.25
USB30_SSTXP: C98.2 J5.23
USB30_VBUS: C99.1 C101.1 J16.1(VBUS) U20.1(OUT)
USER_LED: J5.67 ; also on sheet 17
WLAN_PWR_EN: J6.52 R111.1
N15599533: R84.2 U14.25(RXD0)
N15599537: R85.2 U14.24(RXD1)
N15599541: R87.2 U14.23(RXD2)
N15599545: R88.2 U14.22(RXD3)
N15599549: R89.2 U14.27(RXC)
N15599553: R90.2 U14.26(RXCTL)
N15600826: R95.2 R96.2 U14.31(INTB)
N15601838: C74.1 U14.37(XTAL_OUT) Y2.1
N15601846: C75.1 U14.36(XTAL_IN) Y2.3
N15602572: R104.1 U14.32(LED0)
N15603170: C76.1 J15.1(CT)
N15603215: C77.1 J15.15(SH) J15.16(SH1) R101.1
N15604636: J15.12(GRLC) R100.1
N15605512: R86.1 U14.39(RSET)
N15611443: C100.1 R118.2 U20.4(EN)
N15611553: R121.1 U20.3(ISET)
N15654067: R125.1 U21.3(ISET)
N15752445: J18.G1(GND1) J18.G2(GND2) J18.G3(GND3) J18.G4(GND4) L5.1
N17466585: L3.1 U14.30(REG_OUT)
N17633217: C103.1 U19.3(XOUT) Y3.1
N17633237: C102.2 U19.4(XIN) Y3.3
N17633305: R123.2 U19.18(PSELF)
N17633317: R122.2 U19.16(RESET#/CDP)
N17695706: C128.1 R156.2 U25.4(EN) U26.4(EN)
N17695791: R159.1 U26.3(ISET)
N17695827: R158.1 U25.3(ISET)
N17697466: J15.13(YELC) R99.1
N17770939: R119.1 U19.15(DPU)
N17770942: R120.1 U19.14(DMU)
N18056005: C94.2 Q6.1(GATE) R110.2 R111.2
N18056634: C91.1 C92.1 U15.2(RF0)
N18056637: C91.2 C93.1 CN1.1
N18057325: R109.2 U15.7(D-)
N18057335: R108.2 U15.6(D+)
N18111918: C125.1 R155.2 U24.4(EN) U27.4(EN)
N18111989: R160.1 U27.3(ISET)
N18112037: R157.1 U24.3(ISET)
N18241743: J30.1(SH1) J30.2(SH2) J30.3(SH3) J30.4(SH4) L7.1
N18284542: C123.1 Q8.1(GATE) R130.2
N18285221: Q10.1(GATE) Q11.3(DRAIN) R135.2
N18285616: Q11.1(GATE) R139.1 R142.1
N18287294: Q15.3(DRAIN) R134.2 R136.2
N18287307: Q14.3(DRAIN) R137.2 R138.2
N18287331: Q13.3(DRAIN) R140.2 R141.2
N18287355: Q12.3(DRAIN) R143.2 R144.2
N18437233: R235.1 U38.3(ISET)
N18438798: R236.2 R237.1 U38.4(EN)
N18656178: C104.1 R124.2 U21.4(EN)

Not connected (* = marked no-connect by the designer): J3 25* 27* 31* 33* 35* 37* 39* 41* 43* 45* 47* 49* 53* 55* 57* 59* 61* 63* 66* 70* 72* 74* 76* 78* 80* 84* 86* 88* 90* 92* 94* 96* 98*; J4 40* 42*; J5 3* 5* 7* 9* 13* 15* 20* 22* 24* 26* 29* 30* 31* 32* 35* 36* 37* 38* 39* 40* 41* 42* 43* 45* 47* 49* 53* 55*; J6 3* 4* 5* 6* 7* 9* 10* 11* 12* 13* 15* 16* 17* 18* 21* 22* 23* 24* 26* 28* 32* 34* 36* 38* 51* 53* 55* 57* 59* 61* 63* 65* 91*; J16 14(NC1)* 15(NC2)* 17(NC4)* 18(NC5)*; J19 14*; J20 14*; U15 3(RF1)* 4(XIN)* 9(SUSPEND)* 10(WO_WLAN)* 11(BT_PCM_CLK)* 12(BT_PCM_SYNC)* 13(BT_PCM_OUT)* 14(BT_PCM_IN)*; U19 2(NC1)* 13(LED3/SCL)* 17(NC2)* 19(VDD5)* 21(LED4/SDA)* 22(LED1)* 23(LED2)* 24(PWREN#)*

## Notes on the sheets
sheet 1
- TYPE C Socket
- ESD
- GPIO1_B0
- GPIO1_B1
- TYPE C Power
- CC Handshake Chip
- 100R
- GPIO4_B1
- GPIO0_D3
sheet 2
- WLAN & BT
- Z0=50Ω
- WLAN Power
- GPIO3_C6
sheet 3
- 野火_EBF RK3588S BTB底板_原理图
- 目录
- Page 1
- Content
- Page 2
- Historic Version
- Page 3
- POWER DIAGRAM
- Page 4
- DC IN/POWER/FAN
- Page 5
- DDR4 Connector
- Page 6
- Button/IR/DEBUG/LED
- Page 7
- SD/RS232
- Page 8
- RS485/CAN PORT
- Page 9
- ETH
- Page 10
- WLAN & BT
- Page 11
- USB PORT
- Page 12
- HDMI PORT
- Page 13
- MIPI DSI PORT
- Page 14
- MIPI CSI PORT
- Page 15
- MINI PCIE_PORT
- Page 16
- AUDIO PORT
- Page 17
- TYPE C Socket
- Page 18
sheet 4
- 历史版本
- 版本号
- 日期
- 设计
- 描述
- V0R1
- 2022-12-02
- ghs
- 初始版本
- V0R3
- 2025-02-26
- ghs
- 将GMAC1_TXCLK与GMAC1_TXEN调换线序，修正UART0，UART9线序
- 调整SDMMC引脚线序
- 添加BOOT按钮，修正错误的标注
sheet 5
- Power Diagram
- Switch
- MIPI_DSI0_PORT
- OCP：1A
- MIPI_DSI1_PORT
- DC-DC
- VCC3V3_SYS
- 3.3V 3A
- SYS_LED
- RS232 PORT
- RS485_2
- ETH
- SYS_Switch
- VDD_3V3
- USER_LED
- level Chip
- CAN-1
- WIFI&BT
- VCC_3V3_S3
- OCP：2A
- IR PORT
- RS485_1
- CAN-2
- USB2.0 HUB PHY
- MIPI_CSI_0
- Switch
- MIPI_CSI_1
- OCP：2A
- MIPI_CSI_2
- MIPI_CSI_3
- Switch
- MIPI_DSI_1
- DC IN
- DC-DC
- VCC5V0_SYS
- OCP：1A
- MIPI_DSI_2
- 12V 3A
- 5V 8A
- Core Top Plate
- CAN-1
- CAN-2
- SYS_Switch
- VDD_5V
- HDMI_PORT
- OCP：1A
- Switch
- USB3.0_HOST
- OCP：2A
- Switch
- USB2.0_HOST
- OCP：2A
- Switch
- TYPE C PORT
- OCP：2A
- CC Handshake Chip
- FAN
- NC
- DC-DC
- MINIPCIE_3V3
- 3.3V 3A
- MINI_PCIE
sheet 6
- BTB 0P5 100*4  Connector
- BD ID
- 0R  Automatically start the machine after power on
- NC  Press the ON/OFF button to turn on the device
- Board ID:0x301
- BD_CH3:0.507V
- ADC值:1153
- GPIO4_A6
- GPIO4_A7
- GPIO4_B0
- GPIO4_A0
- GPIO4_A1
- GPIO4_A2
- GPIO4_B4
- GPIO4_B5
- GPIO4_B6
- IO:1.8V
- IO:1.8V
- IO:1.8V
- IO:1.8V
- IO:1.8V
- PCIE20_2_CLKP
- PCIE20_2_CLKN
- GPIO3_A6
- GPIO3_B2
- IO:1.8V
- IO:1.8V
- GPIO0_A0
- GPIO0_B0
- GPIO3_B7
- GPIO3_C0
- IO:1.8V
- GPIO0_B2
- GPIO3_C1
- GPIO3_C6
- GPIO3_C7
- GPIO3_D0
- GPIO0_C4
- GPIO1_C0
- IO:1.8V
- GPIO3_D5
- GPIO4_A3
- GPIO0_C0
- GPIO1_C1
- IO:1.8V
- GPIO4_A4
- GPIO0_C5
- GPIO1_C4
- IO:1.8V
- GPIO4_A5
- GPIO0_B7
- GPIO1_C6
- IO:1.8V
- GPIO4_B1
- GPIO0_D3
- GPIO1_D2
- IO:1.8V
- GPIO0_D0
- GPIO1_D3
- IO:1.8V
- GPIO3_D2
- GPIO0_C6
- GPIO0_C7
- GPIO1_D5
- IO:1.8V
- GPIO3_D1
- GPIO3_D3
- IO:1.8V
- GPIO3_D4
- IO:1.8V
- IO:1.8V
- IO:1.8V
- IO:1.8V
- GPIO1_A2
- IO:1.8V
- GPIO1_A3
- IO:1.8V
- GPIO1_A4
- GPIO1_A7
- GPIO1_A6
- GPIO1_B0
- GPIO1_B1
sheet 7
- ETH
- TXC / RXC : delays 2ns
- PHY Address : 001
- IO use an external
  power supply：3.3V
- L:<200mils
  W:>60mils
- L:<200mils
  W:>60mils
- L:<200mils
- W:>60mils
- GPIO3_C0
- GPIO3_C1
sheet 8
- USB3.0 HOST & USB2.0 HOST
- USB2.0 PORT
- HOST Power
- USB 2.0 HUB PHY
- GPIO4_A4
- 2A限流
- GPIO4_A5
- 2A限流
sheet 9
- HDMI2.1 PORT
- KLXES15AAA1*5
- GPIO1_A4
sheet 10
- MIPI_DSI_TX0 PORT
- MIPI_DSI_TX1 PORT
- GPIO3_B2
- GPIO3_B7
- GPIO0_C0
- PWM0_M2
- GPIO3_D2
- PWM1_M2
- GPIO0_B7
- GPIO4_A3
- MIPI DSI Power
- GPIO1_C1
- GPIO1_C0
- 1A限流
- 1A限流
- 1A限流
- 1A限流
